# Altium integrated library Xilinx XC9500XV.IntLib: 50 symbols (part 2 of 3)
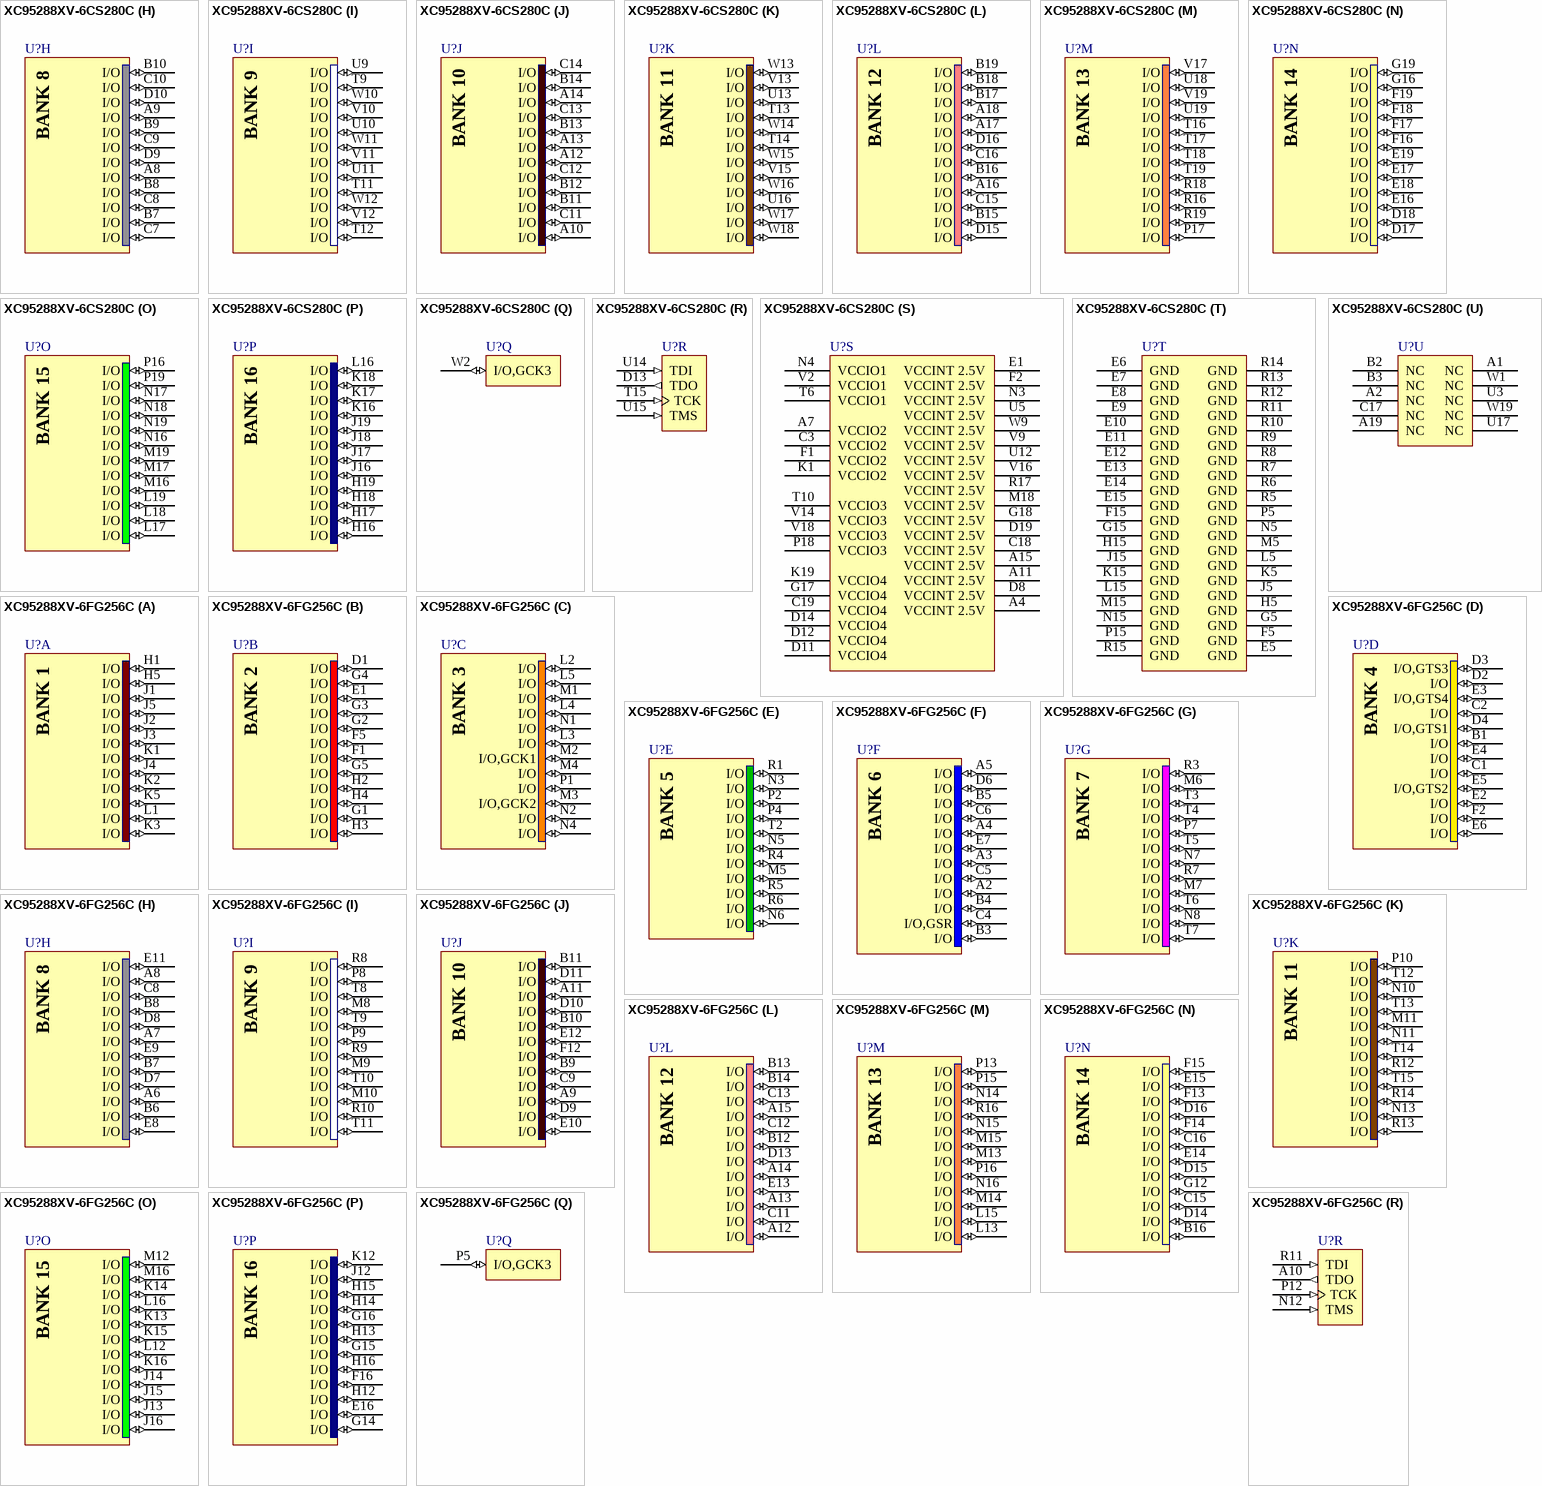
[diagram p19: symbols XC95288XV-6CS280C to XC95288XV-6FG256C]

## XC95288XV-6CS280C
designator U?
XC9500XV, 2.5V High-Performance 288 Macrocell CPLD, 192 User I/Os, 280-Ball CSBGA, Speed Grade 6, Commercial Grade
footprint CS280LAM (BGA, 280-Leads, Body 16x16mm, Pitch 0.8mm)
signal-integrity model XC95288XV_CS280 (XC9500XV)
part A pins: K2 I/O (io), K3 I/O (io), K4 I/O (io), L1 I/O (io), L2 I/O (io), L3 I/O (io), L4 I/O (io), M1 I/O (io), M2 I/O (io), M3 I/O (io), M4 I/O (io), N1 I/O (io)
part B pins: G1 I/O (io), G2 I/O (io), G3 I/O (io), G4 I/O (io), H1 I/O (io), H2 I/O (io), H3 I/O (io), H4 I/O (io), J1 I/O (io), J2 I/O (io), J3 I/O (io), J4 I/O (io)
part C pins: N2 I/O (io), P1 I/O (io), P2 I/O (io), P3 I/O (io), P4 I/O (io), R1 I/O (io), R2 I/O (io), R3 I/O,GCK1 (io), R4 I/O (io), T1 I/O,GCK2 (io), T2 I/O (io), T3 I/O (io)
part D pins: B1 I/O (io), C1 I/O,GTS4 (io), C2 I/O,GTS3 (io), D1 I/O (io), D2 I/O (io), D3 I/O,GTS1 (io), D4 I/O (io), E2 I/O,GTS2 (io), E3 I/O (io), E4 I/O (io), F3 I/O (io), F4 I/O (io)
part E pins: T4 I/O (io), T5 I/O (io), U1 I/O (io), U2 I/O (io), U4 I/O (io), V1 I/O (io), V3 I/O (io), V4 I/O (io), V5 I/O (io), W3 I/O (io), W4 I/O (io)
part F pins: A3 I/O (io), A5 I/O (io), A6 I/O (io), B4 I/O (io), B5 I/O (io), B6 I/O (io), C4 I/O,GSR (io), C5 I/O (io), C6 I/O (io), D5 I/O (io), D6 I/O (io), D7 I/O (io)
part G pins: T7 I/O (io), T8 I/O (io), U6 I/O (io), U7 I/O (io), U8 I/O (io), V6 I/O (io), V7 I/O (io), V8 I/O (io), W5 I/O (io), W6 I/O (io), W7 I/O (io), W8 I/O (io)
part H pins: A8 I/O (io), A9 I/O (io), B7 I/O (io), B8 I/O (io), B9 I/O (io), B10 I/O (io), C7 I/O (io), C8 I/O (io), C9 I/O (io), C10 I/O (io), D9 I/O (io), D10 I/O (io)
part I pins: T9 I/O (io), T11 I/O (io), T12 I/O (io), U9 I/O (io), U10 I/O (io), U11 I/O (io), V10 I/O (io), V11 I/O (io), V12 I/O (io), W10 I/O (io), W11 I/O (io), W12 I/O (io)
part J pins: A10 I/O (io), A12 I/O (io), A13 I/O (io), A14 I/O (io), B11 I/O (io), B12 I/O (io), B13 I/O (io), B14 I/O (io), C11 I/O (io), C12 I/O (io), C13 I/O (io), C14 I/O (io)
part K pins: T13 I/O (io), T14 I/O (io), U13 I/O (io), U16 I/O (io), V13 I/O (io), V15 I/O (io), W13 I/O (io), W14 I/O (io), W15 I/O (io), W16 I/O (io), W17 I/O (io), W18 I/O (io)
part L pins: A16 I/O (io), A17 I/O (io), A18 I/O (io), B15 I/O (io), B16 I/O (io), B17 I/O (io), B18 I/O (io), B19 I/O (io), C15 I/O (io), C16 I/O (io), D15 I/O (io), D16 I/O (io)
part M pins: P17 I/O (io), R16 I/O (io), R18 I/O (io), R19 I/O (io), T16 I/O (io), T17 I/O (io), T18 I/O (io), T19 I/O (io), U18 I/O (io), U19 I/O (io), V17 I/O (io), V19 I/O (io)
part N pins: D17 I/O (io), D18 I/O (io), E16 I/O (io), E17 I/O (io), E18 I/O (io), E19 I/O (io), F16 I/O (io), F17 I/O (io), F18 I/O (io), F19 I/O (io), G16 I/O (io), G19 I/O (io)
part O pins: L17 I/O (io), L18 I/O (io), L19 I/O (io), M16 I/O (io), M17 I/O (io), M19 I/O (io), N16 I/O (io), N17 I/O (io), N18 I/O (io), N19 I/O (io), P16 I/O (io), P19 I/O (io)
part P pins: H16 I/O (io), H17 I/O (io), H18 I/O (io), H19 I/O (io), J16 I/O (io), J17 I/O (io), J18 I/O (io), J19 I/O (io), K16 I/O (io), K17 I/O (io), K18 I/O (io), L16 I/O (io)
part Q pins: W2 I/O,GCK3 (io)
part R pins: D13 TDO (out), T15 TCK (in), U14 TDI (in), U15 TMS (in)
part S pins: A4 VCCINT 2.5V (power), A7 VCCIO2 (power), A11 VCCINT 2.5V (power), A15 VCCINT 2.5V (power), C3 VCCIO2 (power), C18 VCCINT 2.5V (power), C19 VCCIO4 (power), D8 VCCINT 2.5V (power), D11 VCCIO4 (power), D12 VCCIO4 (power), D14 VCCIO4 (power), D19 VCCINT 2.5V (power), E1 VCCINT 2.5V (power), F1 VCCIO2 (power), F2 VCCINT 2.5V (power), G17 VCCIO4 (power), G18 VCCINT 2.5V (power), K1 VCCIO2 (power), K19 VCCIO4 (power), M18 VCCINT 2.5V (power), N3 VCCINT 2.5V (power), N4 VCCIO1 (power), P18 VCCIO3 (power), R17 VCCINT 2.5V (power), T6 VCCIO1 (power), T10 VCCIO3 (power), U5 VCCINT 2.5V (power), U12 VCCINT 2.5V (power), V2 VCCIO1 (power), V9 VCCINT 2.5V (power), V14 VCCIO3 (power), V16 VCCINT 2.5V (power), V18 VCCIO3 (power), W9 VCCINT 2.5V (power)
part T pins: E5 GND (power), E6 GND (power), E7 GND (power), E8 GND (power), E9 GND (power), E10 GND (power), E11 GND (power), E12 GND (power), E13 GND (power), E14 GND (power), E15 GND (power), F5 GND (power), F15 GND (power), G5 GND (power), G15 GND (power), H5 GND (power), H15 GND (power), J5 GND (power), J15 GND (power), K5 GND (power), K15 GND (power), L5 GND (power), L15 GND (power), M5 GND (power), M15 GND (power), N5 GND (power), N15 GND (power), P5 GND (power), P15 GND (power), R5 GND (power), R6 GND (power), R7 GND (power), R8 GND (power), R9 GND (power), R10 GND (power), R11 GND (power), R12 GND (power), R13 GND (power), R14 GND (power), R15 GND (power)
part U pins: A1 NC, A2 NC, A19 NC, B2 NC, B3 NC, C17 NC, U3 NC, U17 NC, W1 NC, W19 NC

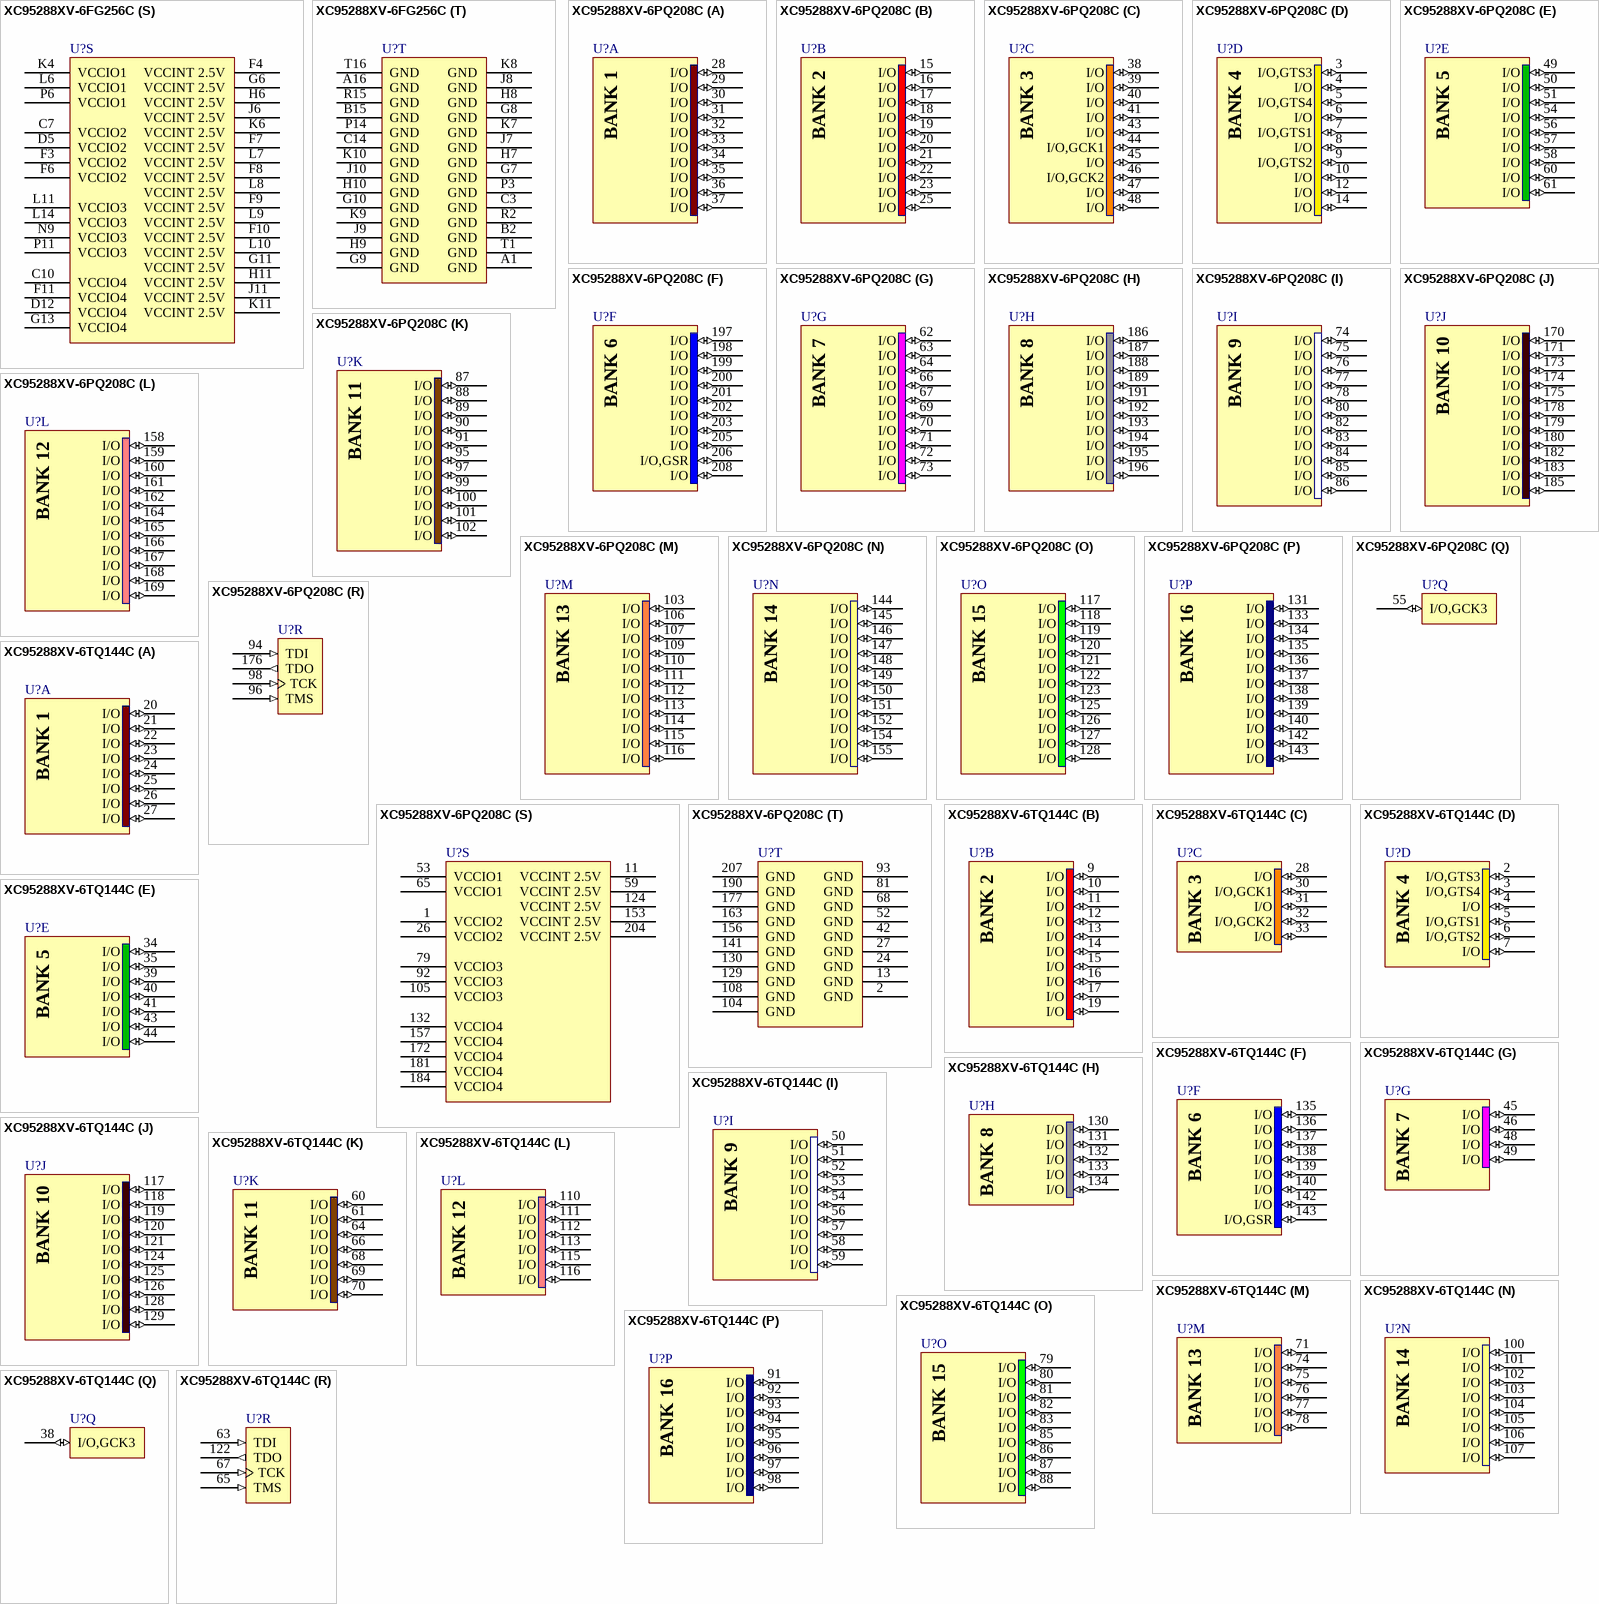
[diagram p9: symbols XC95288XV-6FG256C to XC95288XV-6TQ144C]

## XC95288XV-6FG256C
designator U?
XC9500XV, 2.5V High-Performance 288 Macrocell CPLD, 192 User I/Os, 256-Ball FBGA, Speed Grade 6, Commercial Grade
footprint FG256 (BGA, 256-Leads, Body 17x17mm, Pitch 1mm)
signal-integrity model XC95288XV_FG256 (XC9500XV)
part A pins: H1 I/O (io), H5 I/O (io), J1 I/O (io), J2 I/O (io), J3 I/O (io), J4 I/O (io), J5 I/O (io), K1 I/O (io), K2 I/O (io), K3 I/O (io), K5 I/O (io), L1 I/O (io)
part B pins: D1 I/O (io), E1 I/O (io), F1 I/O (io), F5 I/O (io), G1 I/O (io), G2 I/O (io), G3 I/O (io), G4 I/O (io), G5 I/O (io), H2 I/O (io), H3 I/O (io), H4 I/O (io)
part C pins: L2 I/O (io), L3 I/O (io), L4 I/O (io), L5 I/O (io), M1 I/O (io), M2 I/O,GCK1 (io), M3 I/O,GCK2 (io), M4 I/O (io), N1 I/O (io), N2 I/O (io), N4 I/O (io), P1 I/O (io)
part D pins: B1 I/O (io), C1 I/O (io), C2 I/O (io), D2 I/O (io), D3 I/O,GTS3 (io), D4 I/O,GTS1 (io), E2 I/O (io), E3 I/O,GTS4 (io), E4 I/O (io), E5 I/O,GTS2 (io), E6 I/O (io), F2 I/O (io)
part E pins: M5 I/O (io), N3 I/O (io), N5 I/O (io), N6 I/O (io), P2 I/O (io), P4 I/O (io), R1 I/O (io), R4 I/O (io), R5 I/O (io), R6 I/O (io), T2 I/O (io)
part F pins: A2 I/O (io), A3 I/O (io), A4 I/O (io), A5 I/O (io), B3 I/O (io), B4 I/O (io), B5 I/O (io), C4 I/O,GSR (io), C5 I/O (io), C6 I/O (io), D6 I/O (io), E7 I/O (io)
part G pins: M6 I/O (io), M7 I/O (io), N7 I/O (io), N8 I/O (io), P7 I/O (io), R3 I/O (io), R7 I/O (io), T3 I/O (io), T4 I/O (io), T5 I/O (io), T6 I/O (io), T7 I/O (io)
part H pins: A6 I/O (io), A7 I/O (io), A8 I/O (io), B6 I/O (io), B7 I/O (io), B8 I/O (io), C8 I/O (io), D7 I/O (io), D8 I/O (io), E8 I/O (io), E9 I/O (io), E11 I/O (io)
part I pins: M8 I/O (io), M9 I/O (io), M10 I/O (io), P8 I/O (io), P9 I/O (io), R8 I/O (io), R9 I/O (io), R10 I/O (io), T8 I/O (io), T9 I/O (io), T10 I/O (io), T11 I/O (io)
part J pins: A9 I/O (io), A11 I/O (io), B9 I/O (io), B10 I/O (io), B11 I/O (io), C9 I/O (io), D9 I/O (io), D10 I/O (io), D11 I/O (io), E10 I/O (io), E12 I/O (io), F12 I/O (io)
part K pins: M11 I/O (io), N10 I/O (io), N11 I/O (io), N13 I/O (io), P10 I/O (io), R12 I/O (io), R13 I/O (io), R14 I/O (io), T12 I/O (io), T13 I/O (io), T14 I/O (io), T15 I/O (io)
part L pins: A12 I/O (io), A13 I/O (io), A14 I/O (io), A15 I/O (io), B12 I/O (io), B13 I/O (io), B14 I/O (io), C11 I/O (io), C12 I/O (io), C13 I/O (io), D13 I/O (io), E13 I/O (io)
part M pins: L13 I/O (io), L15 I/O (io), M13 I/O (io), M14 I/O (io), M15 I/O (io), N14 I/O (io), N15 I/O (io), N16 I/O (io), P13 I/O (io), P15 I/O (io), P16 I/O (io), R16 I/O (io)
part N pins: B16 I/O (io), C15 I/O (io), C16 I/O (io), D14 I/O (io), D15 I/O (io), D16 I/O (io), E14 I/O (io), E15 I/O (io), F13 I/O (io), F14 I/O (io), F15 I/O (io), G12 I/O (io)
part O pins: J13 I/O (io), J14 I/O (io), J15 I/O (io), J16 I/O (io), K13 I/O (io), K14 I/O (io), K15 I/O (io), K16 I/O (io), L12 I/O (io), L16 I/O (io), M12 I/O (io), M16 I/O (io)
part P pins: E16 I/O (io), F16 I/O (io), G14 I/O (io), G15 I/O (io), G16 I/O (io), H12 I/O (io), H13 I/O (io), H14 I/O (io), H15 I/O (io), H16 I/O (io), J12 I/O (io), K12 I/O (io)
part Q pins: P5 I/O,GCK3 (io)
part R pins: A10 TDO (out), N12 TMS (in), P12 TCK (in), R11 TDI (in)
part S pins: C7 VCCIO2 (power), C10 VCCIO4 (power), D5 VCCIO2 (power), D12 VCCIO4 (power), F3 VCCIO2 (power), F4 VCCINT 2.5V (power), F6 VCCIO2 (power), F7 VCCINT 2.5V (power), F8 VCCINT 2.5V (power), F9 VCCINT 2.5V (power), F10 VCCINT 2.5V (power), F11 VCCIO4 (power), G6 VCCINT 2.5V (power), G11 VCCINT 2.5V (power), G13 VCCIO4 (power), H6 VCCINT 2.5V (power), H11 VCCINT 2.5V (power), J6 VCCINT 2.5V (power), J11 VCCINT 2.5V (power), K4 VCCIO1 (power), K6 VCCINT 2.5V (power), K11 VCCINT 2.5V (power), L6 VCCIO1 (power), L7 VCCINT 2.5V (power), L8 VCCINT 2.5V (power), L9 VCCINT 2.5V (power), L10 VCCINT 2.5V (power), L11 VCCIO3 (power), L14 VCCIO3 (power), N9 VCCIO3 (power), P6 VCCIO1 (power), P11 VCCIO3 (power)
part T pins: A1 GND (power), A16 GND (power), B2 GND (power), B15 GND (power), C3 GND (power), C14 GND (power), G7 GND (power), G8 GND (power), G9 GND (power), G10 GND (power), H7 GND (power), H8 GND (power), H9 GND (power), H10 GND (power), J7 GND (power), J8 GND (power), J9 GND (power), J10 GND (power), K7 GND (power), K8 GND (power), K9 GND (power), K10 GND (power), P3 GND (power), P14 GND (power), R2 GND (power), R15 GND (power), T1 GND (power), T16 GND (power)

## XC95288XV-6PQ208C
designator U?
XC9500XV, 2.5V High-Performance 288 Macrocell CPLD, 168 User I/Os, 208-Pin PQFP, Speed Grade 6, Commercial Grade
footprint PQ208_N (Shrink QFP, 208-Leads, Body 28x28mm, Pitch 0.5mm, IPC Medium Density)
footprint PQ208_L (Shrink QFP, 208-Leads, Body 28x28mm, Pitch 0.5mm, IPC High Density)
footprint PQ208_M (Shrink QFP, 208-Leads, Body 28x28mm, Pitch 0.5mm, IPC Low Density)
signal-integrity model XC95288XV_PQ208 (XC9500XV)
part A pins: 28 I/O (io), 29 I/O (io), 30 I/O (io), 31 I/O (io), 32 I/O (io), 33 I/O (io), 34 I/O (io), 35 I/O (io), 36 I/O (io), 37 I/O (io)
part B pins: 15 I/O (io), 16 I/O (io), 17 I/O (io), 18 I/O (io), 19 I/O (io), 20 I/O (io), 21 I/O (io), 22 I/O (io), 23 I/O (io), 25 I/O (io)
part C pins: 38 I/O (io), 39 I/O (io), 40 I/O (io), 41 I/O (io), 43 I/O (io), 44 I/O,GCK1 (io), 45 I/O (io), 46 I/O,GCK2 (io), 47 I/O (io), 48 I/O (io)
part D pins: 3 I/O,GTS3 (io), 4 I/O (io), 5 I/O,GTS4 (io), 6 I/O (io), 7 I/O,GTS1 (io), 8 I/O (io), 9 I/O,GTS2 (io), 10 I/O (io), 12 I/O (io), 14 I/O (io)
part E pins: 49 I/O (io), 50 I/O (io), 51 I/O (io), 54 I/O (io), 56 I/O (io), 57 I/O (io), 58 I/O (io), 60 I/O (io), 61 I/O (io)
part F pins: 197 I/O (io), 198 I/O (io), 199 I/O (io), 200 I/O (io), 201 I/O (io), 202 I/O (io), 203 I/O (io), 205 I/O (io), 206 I/O,GSR (io), 208 I/O (io)
part G pins: 62 I/O (io), 63 I/O (io), 64 I/O (io), 66 I/O (io), 67 I/O (io), 69 I/O (io), 70 I/O (io), 71 I/O (io), 72 I/O (io), 73 I/O (io)
part H pins: 186 I/O (io), 187 I/O (io), 188 I/O (io), 189 I/O (io), 191 I/O (io), 192 I/O (io), 193 I/O (io), 194 I/O (io), 195 I/O (io), 196 I/O (io)
part I pins: 74 I/O (io), 75 I/O (io), 76 I/O (io), 77 I/O (io), 78 I/O (io), 80 I/O (io), 82 I/O (io), 83 I/O (io), 84 I/O (io), 85 I/O (io), 86 I/O (io)
part J pins: 170 I/O (io), 171 I/O (io), 173 I/O (io), 174 I/O (io), 175 I/O (io), 178 I/O (io), 179 I/O (io), 180 I/O (io), 182 I/O (io), 183 I/O (io), 185 I/O (io)
part K pins: 87 I/O (io), 88 I/O (io), 89 I/O (io), 90 I/O (io), 91 I/O (io), 95 I/O (io), 97 I/O (io), 99 I/O (io), 100 I/O (io), 101 I/O (io), 102 I/O (io)
part L pins: 158 I/O (io), 159 I/O (io), 160 I/O (io), 161 I/O (io), 162 I/O (io), 164 I/O (io), 165 I/O (io), 166 I/O (io), 167 I/O (io), 168 I/O (io), 169 I/O (io)
part M pins: 103 I/O (io), 106 I/O (io), 107 I/O (io), 109 I/O (io), 110 I/O (io), 111 I/O (io), 112 I/O (io), 113 I/O (io), 114 I/O (io), 115 I/O (io), 116 I/O (io)
part N pins: 144 I/O (io), 145 I/O (io), 146 I/O (io), 147 I/O (io), 148 I/O (io), 149 I/O (io), 150 I/O (io), 151 I/O (io), 152 I/O (io), 154 I/O (io), 155 I/O (io)
part O pins: 117 I/O (io), 118 I/O (io), 119 I/O (io), 120 I/O (io), 121 I/O (io), 122 I/O (io), 123 I/O (io), 125 I/O (io), 126 I/O (io), 127 I/O (io), 128 I/O (io)
part P pins: 131 I/O (io), 133 I/O (io), 134 I/O (io), 135 I/O (io), 136 I/O (io), 137 I/O (io), 138 I/O (io), 139 I/O (io), 140 I/O (io), 142 I/O (io), 143 I/O (io)
part Q pins: 55 I/O,GCK3 (io)
part R pins: 94 TDI (in), 96 TMS (in), 98 TCK (in), 176 TDO (out)
part S pins: 1 VCCIO2 (power), 11 VCCINT 2.5V (power), 26 VCCIO2 (power), 53 VCCIO1 (power), 59 VCCINT 2.5V (power), 65 VCCIO1 (power), 79 VCCIO3 (power), 92 VCCIO3 (power), 105 VCCIO3 (power), 124 VCCINT 2.5V (power), 132 VCCIO4 (power), 153 VCCINT 2.5V (power), 157 VCCIO4 (power), 172 VCCIO4 (power), 181 VCCIO4 (power), 184 VCCIO4 (power), 204 VCCINT 2.5V (power)
part T pins: 2 GND (power), 13 GND (power), 24 GND (power), 27 GND (power), 42 GND (power), 52 GND (power), 68 GND (power), 81 GND (power), 93 GND (power), 104 GND (power), 108 GND (power), 129 GND (power), 130 GND (power), 141 GND (power), 156 GND (power), 163 GND (power), 177 GND (power), 190 GND (power), 207 GND (power)

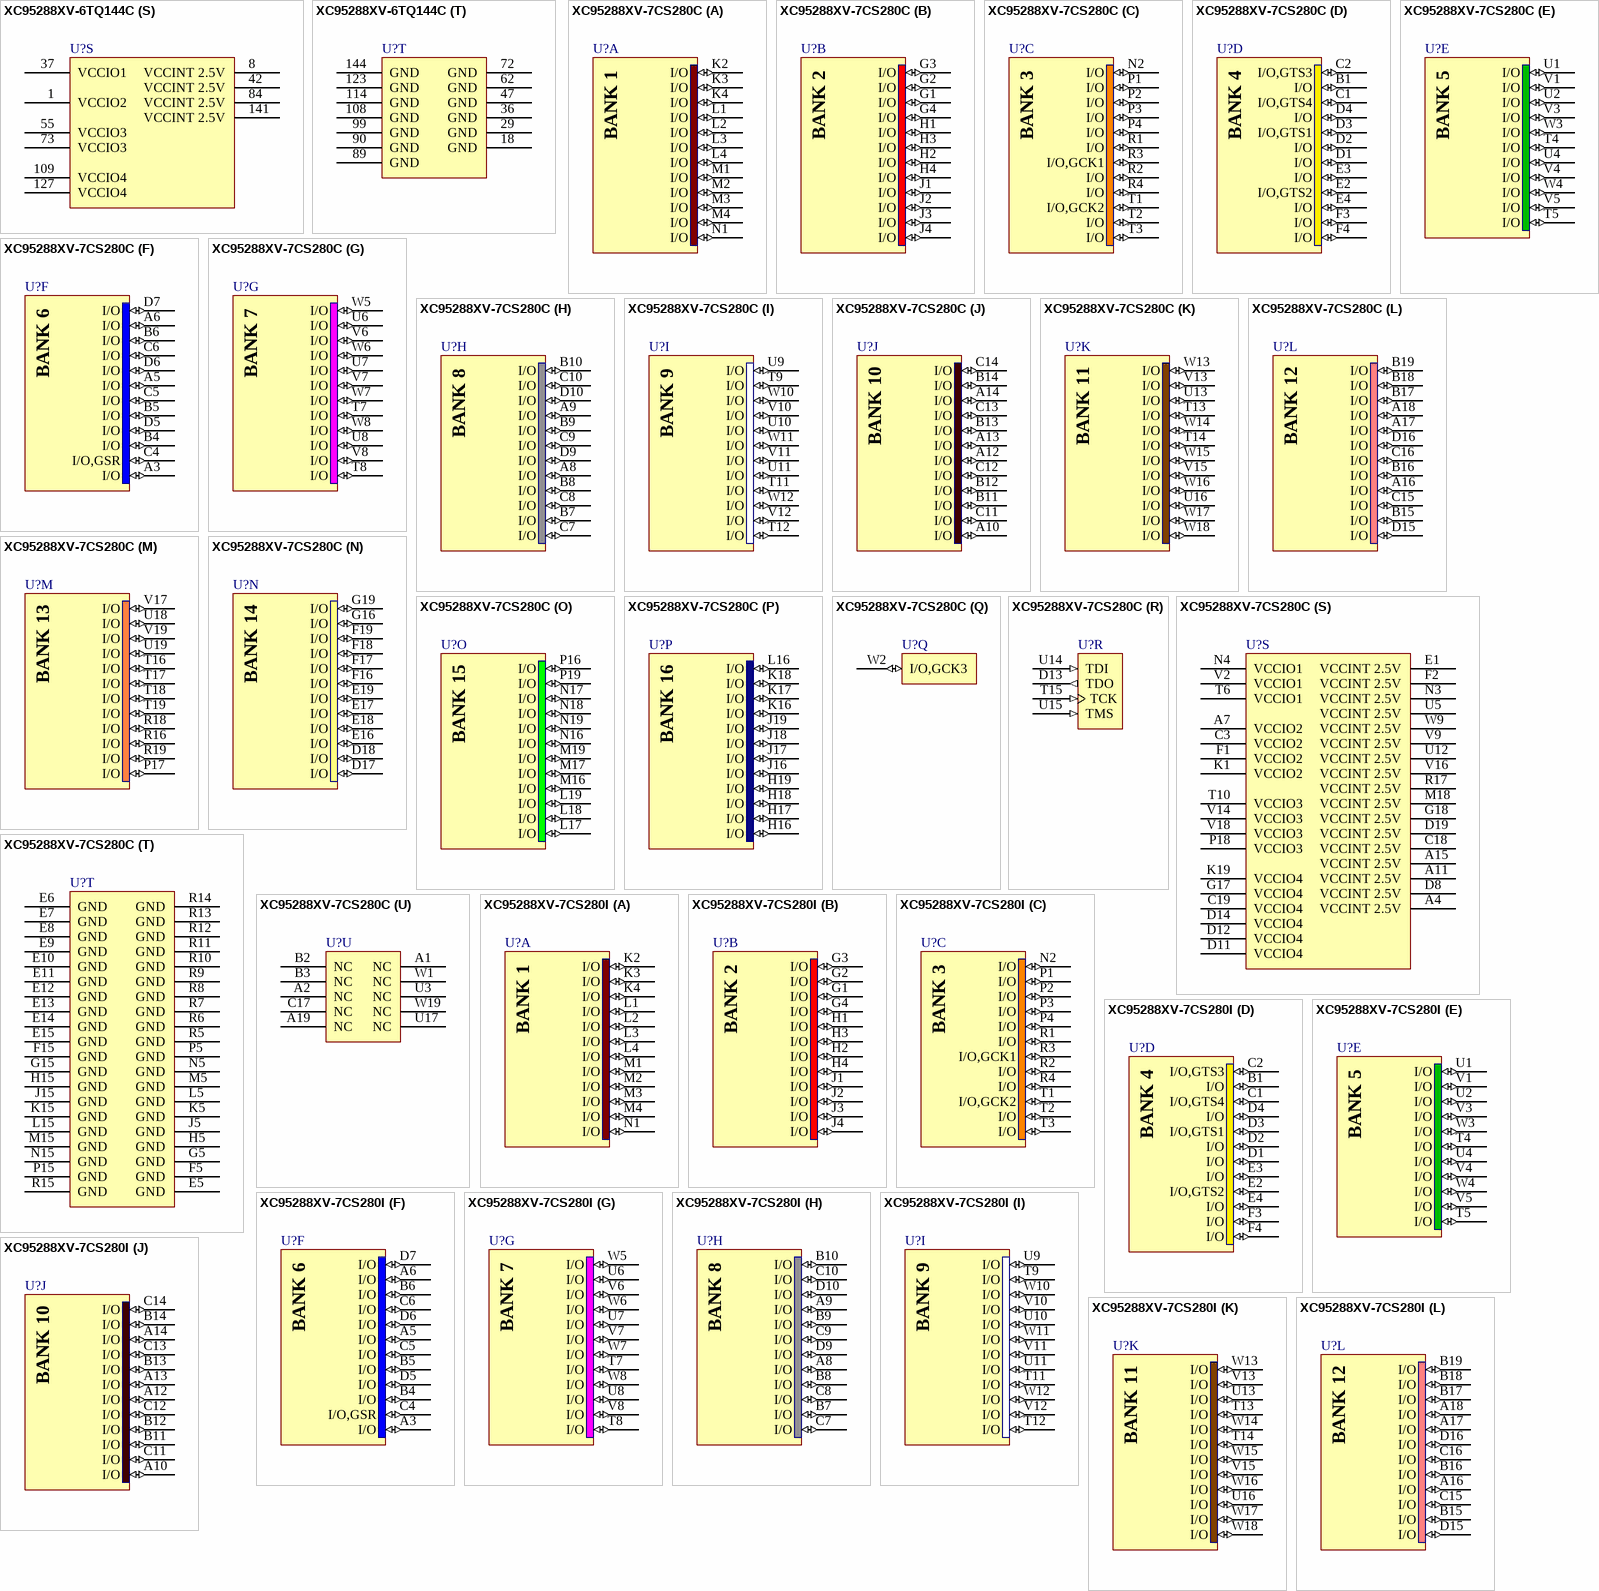
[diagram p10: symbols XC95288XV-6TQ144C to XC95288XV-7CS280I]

## XC95288XV-6TQ144C
designator U?
XC9500XV, 2.5V High-Performance 288 Macrocell CPLD, 117 User I/Os, 144-Pin TQFP, Speed Grade 6, Commercial Grade
footprint TQ144_N (Thin QFP, 144-Leads, Body 20x20mm, Pitch 0.5mm, IPC Medium Density)
footprint TQ144_L (Thin QFP, 144-Leads, Body 20x20mm, Pitch 0.5mm, IPC High Density)
footprint TQ144_M (Thin QFP, 144-Leads, Body 20x20mm, Pitch 0.5mm, IPC Low Density)
signal-integrity model XC95288XV_TQ144 (XC9500XV)
part A pins: 20 I/O (io), 21 I/O (io), 22 I/O (io), 23 I/O (io), 24 I/O (io), 25 I/O (io), 26 I/O (io), 27 I/O (io)
part B pins: 9 I/O (io), 10 I/O (io), 11 I/O (io), 12 I/O (io), 13 I/O (io), 14 I/O (io), 15 I/O (io), 16 I/O (io), 17 I/O (io), 19 I/O (io)
part C pins: 28 I/O (io), 30 I/O,GCK1 (io), 31 I/O (io), 32 I/O,GCK2 (io), 33 I/O (io)
part D pins: 2 I/O,GTS3 (io), 3 I/O,GTS4 (io), 4 I/O (io), 5 I/O,GTS1 (io), 6 I/O,GTS2 (io), 7 I/O (io)
part E pins: 34 I/O (io), 35 I/O (io), 39 I/O (io), 40 I/O (io), 41 I/O (io), 43 I/O (io), 44 I/O (io)
part F pins: 135 I/O (io), 136 I/O (io), 137 I/O (io), 138 I/O (io), 139 I/O (io), 140 I/O (io), 142 I/O (io), 143 I/O,GSR (io)
part G pins: 45 I/O (io), 46 I/O (io), 48 I/O (io), 49 I/O (io)
part H pins: 130 I/O (io), 131 I/O (io), 132 I/O (io), 133 I/O (io), 134 I/O (io)
part I pins: 50 I/O (io), 51 I/O (io), 52 I/O (io), 53 I/O (io), 54 I/O (io), 56 I/O (io), 57 I/O (io), 58 I/O (io), 59 I/O (io)
part J pins: 117 I/O (io), 118 I/O (io), 119 I/O (io), 120 I/O (io), 121 I/O (io), 124 I/O (io), 125 I/O (io), 126 I/O (io), 128 I/O (io), 129 I/O (io)
part K pins: 60 I/O (io), 61 I/O (io), 64 I/O (io), 66 I/O (io), 68 I/O (io), 69 I/O (io), 70 I/O (io)
part L pins: 110 I/O (io), 111 I/O (io), 112 I/O (io), 113 I/O (io), 115 I/O (io), 116 I/O (io)
part M pins: 71 I/O (io), 74 I/O (io), 75 I/O (io), 76 I/O (io), 77 I/O (io), 78 I/O (io)
part N pins: 100 I/O (io), 101 I/O (io), 102 I/O (io), 103 I/O (io), 104 I/O (io), 105 I/O (io), 106 I/O (io), 107 I/O (io)
part O pins: 79 I/O (io), 80 I/O (io), 81 I/O (io), 82 I/O (io), 83 I/O (io), 85 I/O (io), 86 I/O (io), 87 I/O (io), 88 I/O (io)
part P pins: 91 I/O (io), 92 I/O (io), 93 I/O (io), 94 I/O (io), 95 I/O (io), 96 I/O (io), 97 I/O (io), 98 I/O (io)
part Q pins: 38 I/O,GCK3 (io)
part R pins: 63 TDI (in), 65 TMS (in), 67 TCK (in), 122 TDO (out)
part S pins: 1 VCCIO2 (power), 8 VCCINT 2.5V (power), 37 VCCIO1 (power), 42 VCCINT 2.5V (power), 55 VCCIO3 (power), 73 VCCIO3 (power), 84 VCCINT 2.5V (power), 109 VCCIO4 (power), 127 VCCIO4 (power), 141 VCCINT 2.5V (power)
part T pins: 18 GND (power), 29 GND (power), 36 GND (power), 47 GND (power), 62 GND (power), 72 GND (power), 89 GND (power), 90 GND (power), 99 GND (power), 108 GND (power), 114 GND (power), 123 GND (power), 144 GND (power)

## XC95288XV-7CS280C
designator U?
XC9500XV, 2.5V High-Performance 288 Macrocell CPLD, 192 User I/Os, 280-Ball CSBGA, Speed Grade 7, Commercial Grade
footprint CS280LAM (BGA, 280-Leads, Body 16x16mm, Pitch 0.8mm)
signal-integrity model XC95288XV_CS280 (XC9500XV)
part A pins: K2 I/O (io), K3 I/O (io), K4 I/O (io), L1 I/O (io), L2 I/O (io), L3 I/O (io), L4 I/O (io), M1 I/O (io), M2 I/O (io), M3 I/O (io), M4 I/O (io), N1 I/O (io)
part B pins: G1 I/O (io), G2 I/O (io), G3 I/O (io), G4 I/O (io), H1 I/O (io), H2 I/O (io), H3 I/O (io), H4 I/O (io), J1 I/O (io), J2 I/O (io), J3 I/O (io), J4 I/O (io)
part C pins: N2 I/O (io), P1 I/O (io), P2 I/O (io), P3 I/O (io), P4 I/O (io), R1 I/O (io), R2 I/O (io), R3 I/O,GCK1 (io), R4 I/O (io), T1 I/O,GCK2 (io), T2 I/O (io), T3 I/O (io)
part D pins: B1 I/O (io), C1 I/O,GTS4 (io), C2 I/O,GTS3 (io), D1 I/O (io), D2 I/O (io), D3 I/O,GTS1 (io), D4 I/O (io), E2 I/O,GTS2 (io), E3 I/O (io), E4 I/O (io), F3 I/O (io), F4 I/O (io)
part E pins: T4 I/O (io), T5 I/O (io), U1 I/O (io), U2 I/O (io), U4 I/O (io), V1 I/O (io), V3 I/O (io), V4 I/O (io), V5 I/O (io), W3 I/O (io), W4 I/O (io)
part F pins: A3 I/O (io), A5 I/O (io), A6 I/O (io), B4 I/O (io), B5 I/O (io), B6 I/O (io), C4 I/O,GSR (io), C5 I/O (io), C6 I/O (io), D5 I/O (io), D6 I/O (io), D7 I/O (io)
part G pins: T7 I/O (io), T8 I/O (io), U6 I/O (io), U7 I/O (io), U8 I/O (io), V6 I/O (io), V7 I/O (io), V8 I/O (io), W5 I/O (io), W6 I/O (io), W7 I/O (io), W8 I/O (io)
part H pins: A8 I/O (io), A9 I/O (io), B7 I/O (io), B8 I/O (io), B9 I/O (io), B10 I/O (io), C7 I/O (io), C8 I/O (io), C9 I/O (io), C10 I/O (io), D9 I/O (io), D10 I/O (io)
part I pins: T9 I/O (io), T11 I/O (io), T12 I/O (io), U9 I/O (io), U10 I/O (io), U11 I/O (io), V10 I/O (io), V11 I/O (io), V12 I/O (io), W10 I/O (io), W11 I/O (io), W12 I/O (io)
part J pins: A10 I/O (io), A12 I/O (io), A13 I/O (io), A14 I/O (io), B11 I/O (io), B12 I/O (io), B13 I/O (io), B14 I/O (io), C11 I/O (io), C12 I/O (io), C13 I/O (io), C14 I/O (io)
part K pins: T13 I/O (io), T14 I/O (io), U13 I/O (io), U16 I/O (io), V13 I/O (io), V15 I/O (io), W13 I/O (io), W14 I/O (io), W15 I/O (io), W16 I/O (io), W17 I/O (io), W18 I/O (io)
part L pins: A16 I/O (io), A17 I/O (io), A18 I/O (io), B15 I/O (io), B16 I/O (io), B17 I/O (io), B18 I/O (io), B19 I/O (io), C15 I/O (io), C16 I/O (io), D15 I/O (io), D16 I/O (io)
part M pins: P17 I/O (io), R16 I/O (io), R18 I/O (io), R19 I/O (io), T16 I/O (io), T17 I/O (io), T18 I/O (io), T19 I/O (io), U18 I/O (io), U19 I/O (io), V17 I/O (io), V19 I/O (io)
part N pins: D17 I/O (io), D18 I/O (io), E16 I/O (io), E17 I/O (io), E18 I/O (io), E19 I/O (io), F16 I/O (io), F17 I/O (io), F18 I/O (io), F19 I/O (io), G16 I/O (io), G19 I/O (io)
part O pins: L17 I/O (io), L18 I/O (io), L19 I/O (io), M16 I/O (io), M17 I/O (io), M19 I/O (io), N16 I/O (io), N17 I/O (io), N18 I/O (io), N19 I/O (io), P16 I/O (io), P19 I/O (io)
part P pins: H16 I/O (io), H17 I/O (io), H18 I/O (io), H19 I/O (io), J16 I/O (io), J17 I/O (io), J18 I/O (io), J19 I/O (io), K16 I/O (io), K17 I/O (io), K18 I/O (io), L16 I/O (io)
part Q pins: W2 I/O,GCK3 (io)
part R pins: D13 TDO (out), T15 TCK (in), U14 TDI (in), U15 TMS (in)
part S pins: A4 VCCINT 2.5V (power), A7 VCCIO2 (power), A11 VCCINT 2.5V (power), A15 VCCINT 2.5V (power), C3 VCCIO2 (power), C18 VCCINT 2.5V (power), C19 VCCIO4 (power), D8 VCCINT 2.5V (power), D11 VCCIO4 (power), D12 VCCIO4 (power), D14 VCCIO4 (power), D19 VCCINT 2.5V (power), E1 VCCINT 2.5V (power), F1 VCCIO2 (power), F2 VCCINT 2.5V (power), G17 VCCIO4 (power), G18 VCCINT 2.5V (power), K1 VCCIO2 (power), K19 VCCIO4 (power), M18 VCCINT 2.5V (power), N3 VCCINT 2.5V (power), N4 VCCIO1 (power), P18 VCCIO3 (power), R17 VCCINT 2.5V (power), T6 VCCIO1 (power), T10 VCCIO3 (power), U5 VCCINT 2.5V (power), U12 VCCINT 2.5V (power), V2 VCCIO1 (power), V9 VCCINT 2.5V (power), V14 VCCIO3 (power), V16 VCCINT 2.5V (power), V18 VCCIO3 (power), W9 VCCINT 2.5V (power)
part T pins: E5 GND (power), E6 GND (power), E7 GND (power), E8 GND (power), E9 GND (power), E10 GND (power), E11 GND (power), E12 GND (power), E13 GND (power), E14 GND (power), E15 GND (power), F5 GND (power), F15 GND (power), G5 GND (power), G15 GND (power), H5 GND (power), H15 GND (power), J5 GND (power), J15 GND (power), K5 GND (power), K15 GND (power), L5 GND (power), L15 GND (power), M5 GND (power), M15 GND (power), N5 GND (power), N15 GND (power), P5 GND (power), P15 GND (power), R5 GND (power), R6 GND (power), R7 GND (power), R8 GND (power), R9 GND (power), R10 GND (power), R11 GND (power), R12 GND (power), R13 GND (power), R14 GND (power), R15 GND (power)
part U pins: A1 NC, A2 NC, A19 NC, B2 NC, B3 NC, C17 NC, U3 NC, U17 NC, W1 NC, W19 NC

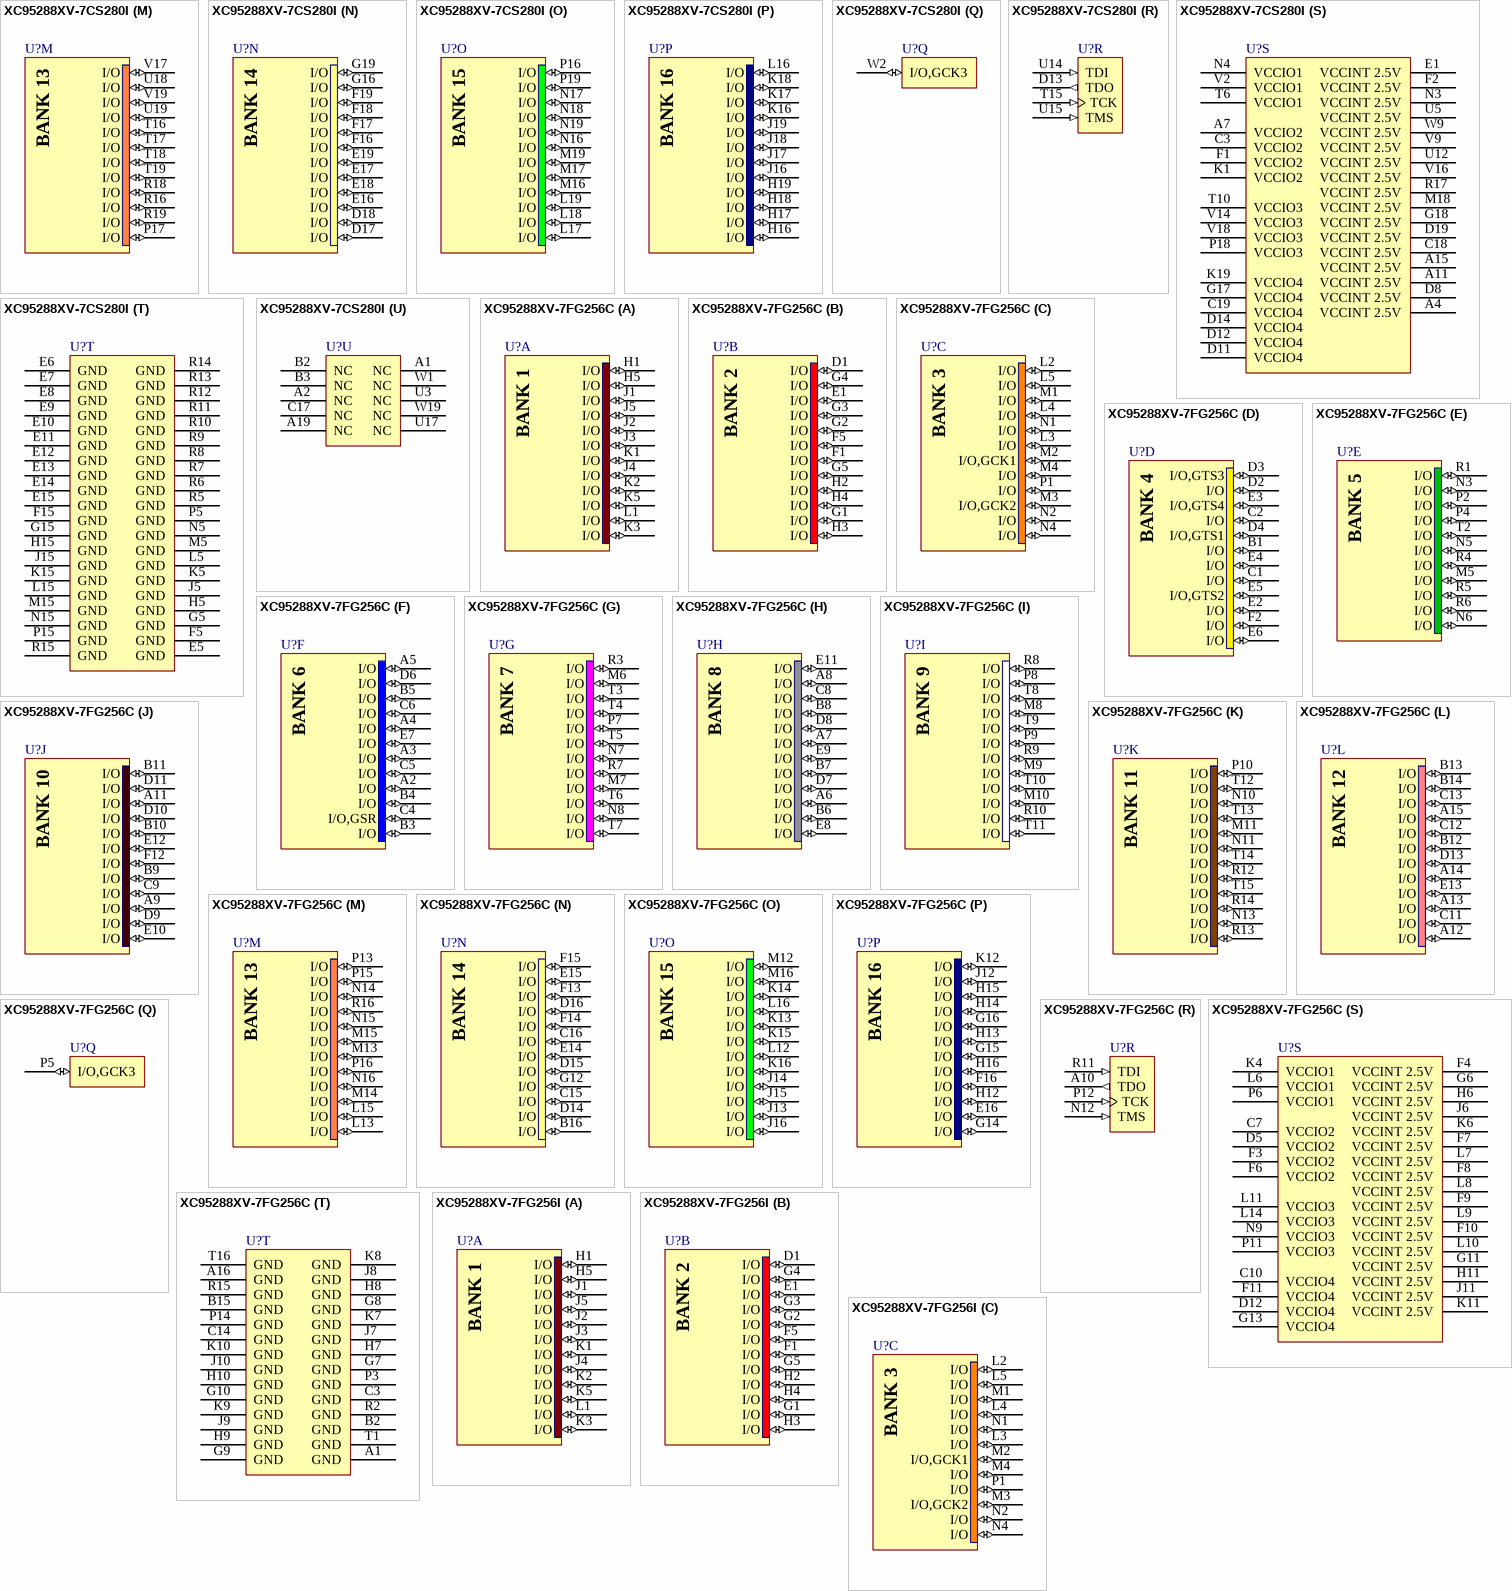
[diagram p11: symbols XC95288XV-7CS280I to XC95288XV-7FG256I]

## XC95288XV-7CS280I
designator U?
XC9500XV, 2.5V High-Performance 288 Macrocell CPLD, 192 User I/Os, 280-Ball CSBGA, Speed Grade 7, Industrial Grade
footprint CS280LAM (BGA, 280-Leads, Body 16x16mm, Pitch 0.8mm)
signal-integrity model XC95288XV_CS280 (XC9500XV)
part A pins: K2 I/O (io), K3 I/O (io), K4 I/O (io), L1 I/O (io), L2 I/O (io), L3 I/O (io), L4 I/O (io), M1 I/O (io), M2 I/O (io), M3 I/O (io), M4 I/O (io), N1 I/O (io)
part B pins: G1 I/O (io), G2 I/O (io), G3 I/O (io), G4 I/O (io), H1 I/O (io), H2 I/O (io), H3 I/O (io), H4 I/O (io), J1 I/O (io), J2 I/O (io), J3 I/O (io), J4 I/O (io)
part C pins: N2 I/O (io), P1 I/O (io), P2 I/O (io), P3 I/O (io), P4 I/O (io), R1 I/O (io), R2 I/O (io), R3 I/O,GCK1 (io), R4 I/O (io), T1 I/O,GCK2 (io), T2 I/O (io), T3 I/O (io)
part D pins: B1 I/O (io), C1 I/O,GTS4 (io), C2 I/O,GTS3 (io), D1 I/O (io), D2 I/O (io), D3 I/O,GTS1 (io), D4 I/O (io), E2 I/O,GTS2 (io), E3 I/O (io), E4 I/O (io), F3 I/O (io), F4 I/O (io)
part E pins: T4 I/O (io), T5 I/O (io), U1 I/O (io), U2 I/O (io), U4 I/O (io), V1 I/O (io), V3 I/O (io), V4 I/O (io), V5 I/O (io), W3 I/O (io), W4 I/O (io)
part F pins: A3 I/O (io), A5 I/O (io), A6 I/O (io), B4 I/O (io), B5 I/O (io), B6 I/O (io), C4 I/O,GSR (io), C5 I/O (io), C6 I/O (io), D5 I/O (io), D6 I/O (io), D7 I/O (io)
part G pins: T7 I/O (io), T8 I/O (io), U6 I/O (io), U7 I/O (io), U8 I/O (io), V6 I/O (io), V7 I/O (io), V8 I/O (io), W5 I/O (io), W6 I/O (io), W7 I/O (io), W8 I/O (io)
part H pins: A8 I/O (io), A9 I/O (io), B7 I/O (io), B8 I/O (io), B9 I/O (io), B10 I/O (io), C7 I/O (io), C8 I/O (io), C9 I/O (io), C10 I/O (io), D9 I/O (io), D10 I/O (io)
part I pins: T9 I/O (io), T11 I/O (io), T12 I/O (io), U9 I/O (io), U10 I/O (io), U11 I/O (io), V10 I/O (io), V11 I/O (io), V12 I/O (io), W10 I/O (io), W11 I/O (io), W12 I/O (io)
part J pins: A10 I/O (io), A12 I/O (io), A13 I/O (io), A14 I/O (io), B11 I/O (io), B12 I/O (io), B13 I/O (io), B14 I/O (io), C11 I/O (io), C12 I/O (io), C13 I/O (io), C14 I/O (io)
part K pins: T13 I/O (io), T14 I/O (io), U13 I/O (io), U16 I/O (io), V13 I/O (io), V15 I/O (io), W13 I/O (io), W14 I/O (io), W15 I/O (io), W16 I/O (io), W17 I/O (io), W18 I/O (io)
part L pins: A16 I/O (io), A17 I/O (io), A18 I/O (io), B15 I/O (io), B16 I/O (io), B17 I/O (io), B18 I/O (io), B19 I/O (io), C15 I/O (io), C16 I/O (io), D15 I/O (io), D16 I/O (io)
part M pins: P17 I/O (io), R16 I/O (io), R18 I/O (io), R19 I/O (io), T16 I/O (io), T17 I/O (io), T18 I/O (io), T19 I/O (io), U18 I/O (io), U19 I/O (io), V17 I/O (io), V19 I/O (io)
part N pins: D17 I/O (io), D18 I/O (io), E16 I/O (io), E17 I/O (io), E18 I/O (io), E19 I/O (io), F16 I/O (io), F17 I/O (io), F18 I/O (io), F19 I/O (io), G16 I/O (io), G19 I/O (io)
part O pins: L17 I/O (io), L18 I/O (io), L19 I/O (io), M16 I/O (io), M17 I/O (io), M19 I/O (io), N16 I/O (io), N17 I/O (io), N18 I/O (io), N19 I/O (io), P16 I/O (io), P19 I/O (io)
part P pins: H16 I/O (io), H17 I/O (io), H18 I/O (io), H19 I/O (io), J16 I/O (io), J17 I/O (io), J18 I/O (io), J19 I/O (io), K16 I/O (io), K17 I/O (io), K18 I/O (io), L16 I/O (io)
part Q pins: W2 I/O,GCK3 (io)
part R pins: D13 TDO (out), T15 TCK (in), U14 TDI (in), U15 TMS (in)
part S pins: A4 VCCINT 2.5V (power), A7 VCCIO2 (power), A11 VCCINT 2.5V (power), A15 VCCINT 2.5V (power), C3 VCCIO2 (power), C18 VCCINT 2.5V (power), C19 VCCIO4 (power), D8 VCCINT 2.5V (power), D11 VCCIO4 (power), D12 VCCIO4 (power), D14 VCCIO4 (power), D19 VCCINT 2.5V (power), E1 VCCINT 2.5V (power), F1 VCCIO2 (power), F2 VCCINT 2.5V (power), G17 VCCIO4 (power), G18 VCCINT 2.5V (power), K1 VCCIO2 (power), K19 VCCIO4 (power), M18 VCCINT 2.5V (power), N3 VCCINT 2.5V (power), N4 VCCIO1 (power), P18 VCCIO3 (power), R17 VCCINT 2.5V (power), T6 VCCIO1 (power), T10 VCCIO3 (power), U5 VCCINT 2.5V (power), U12 VCCINT 2.5V (power), V2 VCCIO1 (power), V9 VCCINT 2.5V (power), V14 VCCIO3 (power), V16 VCCINT 2.5V (power), V18 VCCIO3 (power), W9 VCCINT 2.5V (power)
part T pins: E5 GND (power), E6 GND (power), E7 GND (power), E8 GND (power), E9 GND (power), E10 GND (power), E11 GND (power), E12 GND (power), E13 GND (power), E14 GND (power), E15 GND (power), F5 GND (power), F15 GND (power), G5 GND (power), G15 GND (power), H5 GND (power), H15 GND (power), J5 GND (power), J15 GND (power), K5 GND (power), K15 GND (power), L5 GND (power), L15 GND (power), M5 GND (power), M15 GND (power), N5 GND (power), N15 GND (power), P5 GND (power), P15 GND (power), R5 GND (power), R6 GND (power), R7 GND (power), R8 GND (power), R9 GND (power), R10 GND (power), R11 GND (power), R12 GND (power), R13 GND (power), R14 GND (power), R15 GND (power)
part U pins: A1 NC, A2 NC, A19 NC, B2 NC, B3 NC, C17 NC, U3 NC, U17 NC, W1 NC, W19 NC

## XC95288XV-7FG256C
designator U?
XC9500XV, 2.5V High-Performance 288 Macrocell CPLD, 192 User I/Os, 256-Ball FBGA, Speed Grade 7, Commercial Grade
footprint FG256 (BGA, 256-Leads, Body 17x17mm, Pitch 1mm)
signal-integrity model XC95288XV_FG256 (XC9500XV)
part A pins: H1 I/O (io), H5 I/O (io), J1 I/O (io), J2 I/O (io), J3 I/O (io), J4 I/O (io), J5 I/O (io), K1 I/O (io), K2 I/O (io), K3 I/O (io), K5 I/O (io), L1 I/O (io)
part B pins: D1 I/O (io), E1 I/O (io), F1 I/O (io), F5 I/O (io), G1 I/O (io), G2 I/O (io), G3 I/O (io), G4 I/O (io), G5 I/O (io), H2 I/O (io), H3 I/O (io), H4 I/O (io)
part C pins: L2 I/O (io), L3 I/O (io), L4 I/O (io), L5 I/O (io), M1 I/O (io), M2 I/O,GCK1 (io), M3 I/O,GCK2 (io), M4 I/O (io), N1 I/O (io), N2 I/O (io), N4 I/O (io), P1 I/O (io)
part D pins: B1 I/O (io), C1 I/O (io), C2 I/O (io), D2 I/O (io), D3 I/O,GTS3 (io), D4 I/O,GTS1 (io), E2 I/O (io), E3 I/O,GTS4 (io), E4 I/O (io), E5 I/O,GTS2 (io), E6 I/O (io), F2 I/O (io)
part E pins: M5 I/O (io), N3 I/O (io), N5 I/O (io), N6 I/O (io), P2 I/O (io), P4 I/O (io), R1 I/O (io), R4 I/O (io), R5 I/O (io), R6 I/O (io), T2 I/O (io)
part F pins: A2 I/O (io), A3 I/O (io), A4 I/O (io), A5 I/O (io), B3 I/O (io), B4 I/O (io), B5 I/O (io), C4 I/O,GSR (io), C5 I/O (io), C6 I/O (io), D6 I/O (io), E7 I/O (io)
part G pins: M6 I/O (io), M7 I/O (io), N7 I/O (io), N8 I/O (io), P7 I/O (io), R3 I/O (io), R7 I/O (io), T3 I/O (io), T4 I/O (io), T5 I/O (io), T6 I/O (io), T7 I/O (io)
part H pins: A6 I/O (io), A7 I/O (io), A8 I/O (io), B6 I/O (io), B7 I/O (io), B8 I/O (io), C8 I/O (io), D7 I/O (io), D8 I/O (io), E8 I/O (io), E9 I/O (io), E11 I/O (io)
part I pins: M8 I/O (io), M9 I/O (io), M10 I/O (io), P8 I/O (io), P9 I/O (io), R8 I/O (io), R9 I/O (io), R10 I/O (io), T8 I/O (io), T9 I/O (io), T10 I/O (io), T11 I/O (io)
part J pins: A9 I/O (io), A11 I/O (io), B9 I/O (io), B10 I/O (io), B11 I/O (io), C9 I/O (io), D9 I/O (io), D10 I/O (io), D11 I/O (io), E10 I/O (io), E12 I/O (io), F12 I/O (io)
part K pins: M11 I/O (io), N10 I/O (io), N11 I/O (io), N13 I/O (io), P10 I/O (io), R12 I/O (io), R13 I/O (io), R14 I/O (io), T12 I/O (io), T13 I/O (io), T14 I/O (io), T15 I/O (io)
part L pins: A12 I/O (io), A13 I/O (io), A14 I/O (io), A15 I/O (io), B12 I/O (io), B13 I/O (io), B14 I/O (io), C11 I/O (io), C12 I/O (io), C13 I/O (io), D13 I/O (io), E13 I/O (io)
part M pins: L13 I/O (io), L15 I/O (io), M13 I/O (io), M14 I/O (io), M15 I/O (io), N14 I/O (io), N15 I/O (io), N16 I/O (io), P13 I/O (io), P15 I/O (io), P16 I/O (io), R16 I/O (io)
part N pins: B16 I/O (io), C15 I/O (io), C16 I/O (io), D14 I/O (io), D15 I/O (io), D16 I/O (io), E14 I/O (io), E15 I/O (io), F13 I/O (io), F14 I/O (io), F15 I/O (io), G12 I/O (io)
part O pins: J13 I/O (io), J14 I/O (io), J15 I/O (io), J16 I/O (io), K13 I/O (io), K14 I/O (io), K15 I/O (io), K16 I/O (io), L12 I/O (io), L16 I/O (io), M12 I/O (io), M16 I/O (io)
part P pins: E16 I/O (io), F16 I/O (io), G14 I/O (io), G15 I/O (io), G16 I/O (io), H12 I/O (io), H13 I/O (io), H14 I/O (io), H15 I/O (io), H16 I/O (io), J12 I/O (io), K12 I/O (io)
part Q pins: P5 I/O,GCK3 (io)
part R pins: A10 TDO (out), N12 TMS (in), P12 TCK (in), R11 TDI (in)
part S pins: C7 VCCIO2 (power), C10 VCCIO4 (power), D5 VCCIO2 (power), D12 VCCIO4 (power), F3 VCCIO2 (power), F4 VCCINT 2.5V (power), F6 VCCIO2 (power), F7 VCCINT 2.5V (power), F8 VCCINT 2.5V (power), F9 VCCINT 2.5V (power), F10 VCCINT 2.5V (power), F11 VCCIO4 (power), G6 VCCINT 2.5V (power), G11 VCCINT 2.5V (power), G13 VCCIO4 (power), H6 VCCINT 2.5V (power), H11 VCCINT 2.5V (power), J6 VCCINT 2.5V (power), J11 VCCINT 2.5V (power), K4 VCCIO1 (power), K6 VCCINT 2.5V (power), K11 VCCINT 2.5V (power), L6 VCCIO1 (power), L7 VCCINT 2.5V (power), L8 VCCINT 2.5V (power), L9 VCCINT 2.5V (power), L10 VCCINT 2.5V (power), L11 VCCIO3 (power), L14 VCCIO3 (power), N9 VCCIO3 (power), P6 VCCIO1 (power), P11 VCCIO3 (power)
part T pins: A1 GND (power), A16 GND (power), B2 GND (power), B15 GND (power), C3 GND (power), C14 GND (power), G7 GND (power), G8 GND (power), G9 GND (power), G10 GND (power), H7 GND (power), H8 GND (power), H9 GND (power), H10 GND (power), J7 GND (power), J8 GND (power), J9 GND (power), J10 GND (power), K7 GND (power), K8 GND (power), K9 GND (power), K10 GND (power), P3 GND (power), P14 GND (power), R2 GND (power), R15 GND (power), T1 GND (power), T16 GND (power)

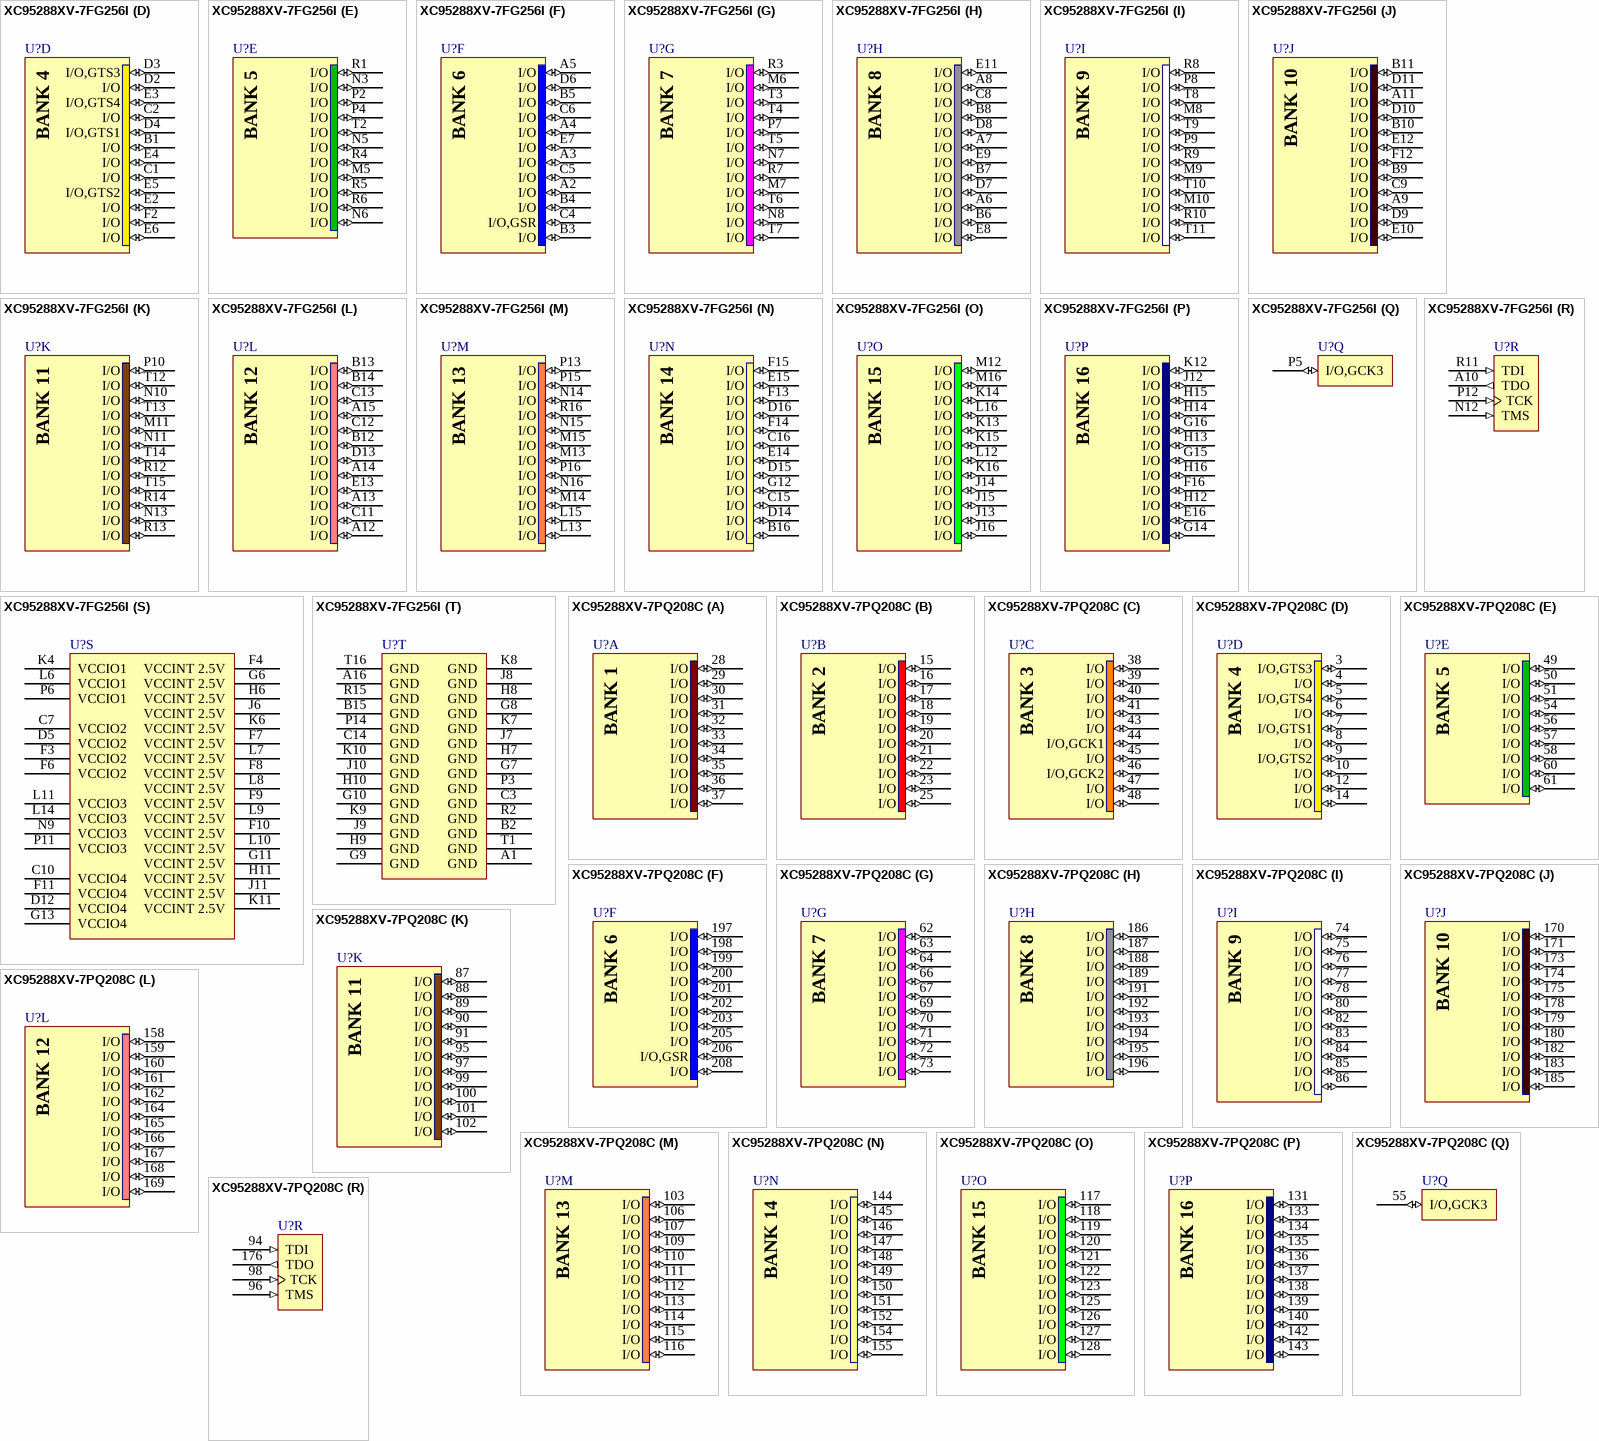
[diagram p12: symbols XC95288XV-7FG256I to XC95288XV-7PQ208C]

## XC95288XV-7FG256I
designator U?
XC9500XV, 2.5V High-Performance 288 Macrocell CPLD, 192 User I/Os, 256-Ball FBGA, Speed Grade 7, Industrial Grade
footprint FG256 (BGA, 256-Leads, Body 17x17mm, Pitch 1mm)
signal-integrity model XC95288XV_FG256 (XC9500XV)
part A pins: H1 I/O (io), H5 I/O (io), J1 I/O (io), J2 I/O (io), J3 I/O (io), J4 I/O (io), J5 I/O (io), K1 I/O (io), K2 I/O (io), K3 I/O (io), K5 I/O (io), L1 I/O (io)
part B pins: D1 I/O (io), E1 I/O (io), F1 I/O (io), F5 I/O (io), G1 I/O (io), G2 I/O (io), G3 I/O (io), G4 I/O (io), G5 I/O (io), H2 I/O (io), H3 I/O (io), H4 I/O (io)
part C pins: L2 I/O (io), L3 I/O (io), L4 I/O (io), L5 I/O (io), M1 I/O (io), M2 I/O,GCK1 (io), M3 I/O,GCK2 (io), M4 I/O (io), N1 I/O (io), N2 I/O (io), N4 I/O (io), P1 I/O (io)
part D pins: B1 I/O (io), C1 I/O (io), C2 I/O (io), D2 I/O (io), D3 I/O,GTS3 (io), D4 I/O,GTS1 (io), E2 I/O (io), E3 I/O,GTS4 (io), E4 I/O (io), E5 I/O,GTS2 (io), E6 I/O (io), F2 I/O (io)
part E pins: M5 I/O (io), N3 I/O (io), N5 I/O (io), N6 I/O (io), P2 I/O (io), P4 I/O (io), R1 I/O (io), R4 I/O (io), R5 I/O (io), R6 I/O (io), T2 I/O (io)
part F pins: A2 I/O (io), A3 I/O (io), A4 I/O (io), A5 I/O (io), B3 I/O (io), B4 I/O (io), B5 I/O (io), C4 I/O,GSR (io), C5 I/O (io), C6 I/O (io), D6 I/O (io), E7 I/O (io)
part G pins: M6 I/O (io), M7 I/O (io), N7 I/O (io), N8 I/O (io), P7 I/O (io), R3 I/O (io), R7 I/O (io), T3 I/O (io), T4 I/O (io), T5 I/O (io), T6 I/O (io), T7 I/O (io)
part H pins: A6 I/O (io), A7 I/O (io), A8 I/O (io), B6 I/O (io), B7 I/O (io), B8 I/O (io), C8 I/O (io), D7 I/O (io), D8 I/O (io), E8 I/O (io), E9 I/O (io), E11 I/O (io)
part I pins: M8 I/O (io), M9 I/O (io), M10 I/O (io), P8 I/O (io), P9 I/O (io), R8 I/O (io), R9 I/O (io), R10 I/O (io), T8 I/O (io), T9 I/O (io), T10 I/O (io), T11 I/O (io)
part J pins: A9 I/O (io), A11 I/O (io), B9 I/O (io), B10 I/O (io), B11 I/O (io), C9 I/O (io), D9 I/O (io), D10 I/O (io), D11 I/O (io), E10 I/O (io), E12 I/O (io), F12 I/O (io)
part K pins: M11 I/O (io), N10 I/O (io), N11 I/O (io), N13 I/O (io), P10 I/O (io), R12 I/O (io), R13 I/O (io), R14 I/O (io), T12 I/O (io), T13 I/O (io), T14 I/O (io), T15 I/O (io)
part L pins: A12 I/O (io), A13 I/O (io), A14 I/O (io), A15 I/O (io), B12 I/O (io), B13 I/O (io), B14 I/O (io), C11 I/O (io), C12 I/O (io), C13 I/O (io), D13 I/O (io), E13 I/O (io)
part M pins: L13 I/O (io), L15 I/O (io), M13 I/O (io), M14 I/O (io), M15 I/O (io), N14 I/O (io), N15 I/O (io), N16 I/O (io), P13 I/O (io), P15 I/O (io), P16 I/O (io), R16 I/O (io)
part N pins: B16 I/O (io), C15 I/O (io), C16 I/O (io), D14 I/O (io), D15 I/O (io), D16 I/O (io), E14 I/O (io), E15 I/O (io), F13 I/O (io), F14 I/O (io), F15 I/O (io), G12 I/O (io)
part O pins: J13 I/O (io), J14 I/O (io), J15 I/O (io), J16 I/O (io), K13 I/O (io), K14 I/O (io), K15 I/O (io), K16 I/O (io), L12 I/O (io), L16 I/O (io), M12 I/O (io), M16 I/O (io)
part P pins: E16 I/O (io), F16 I/O (io), G14 I/O (io), G15 I/O (io), G16 I/O (io), H12 I/O (io), H13 I/O (io), H14 I/O (io), H15 I/O (io), H16 I/O (io), J12 I/O (io), K12 I/O (io)
part Q pins: P5 I/O,GCK3 (io)
part R pins: A10 TDO (out), N12 TMS (in), P12 TCK (in), R11 TDI (in)
part S pins: C7 VCCIO2 (power), C10 VCCIO4 (power), D5 VCCIO2 (power), D12 VCCIO4 (power), F3 VCCIO2 (power), F4 VCCINT 2.5V (power), F6 VCCIO2 (power), F7 VCCINT 2.5V (power), F8 VCCINT 2.5V (power), F9 VCCINT 2.5V (power), F10 VCCINT 2.5V (power), F11 VCCIO4 (power), G6 VCCINT 2.5V (power), G11 VCCINT 2.5V (power), G13 VCCIO4 (power), H6 VCCINT 2.5V (power), H11 VCCINT 2.5V (power), J6 VCCINT 2.5V (power), J11 VCCINT 2.5V (power), K4 VCCIO1 (power), K6 VCCINT 2.5V (power), K11 VCCINT 2.5V (power), L6 VCCIO1 (power), L7 VCCINT 2.5V (power), L8 VCCINT 2.5V (power), L9 VCCINT 2.5V (power), L10 VCCINT 2.5V (power), L11 VCCIO3 (power), L14 VCCIO3 (power), N9 VCCIO3 (power), P6 VCCIO1 (power), P11 VCCIO3 (power)
part T pins: A1 GND (power), A16 GND (power), B2 GND (power), B15 GND (power), C3 GND (power), C14 GND (power), G7 GND (power), G8 GND (power), G9 GND (power), G10 GND (power), H7 GND (power), H8 GND (power), H9 GND (power), H10 GND (power), J7 GND (power), J8 GND (power), J9 GND (power), J10 GND (power), K7 GND (power), K8 GND (power), K9 GND (power), K10 GND (power), P3 GND (power), P14 GND (power), R2 GND (power), R15 GND (power), T1 GND (power), T16 GND (power)

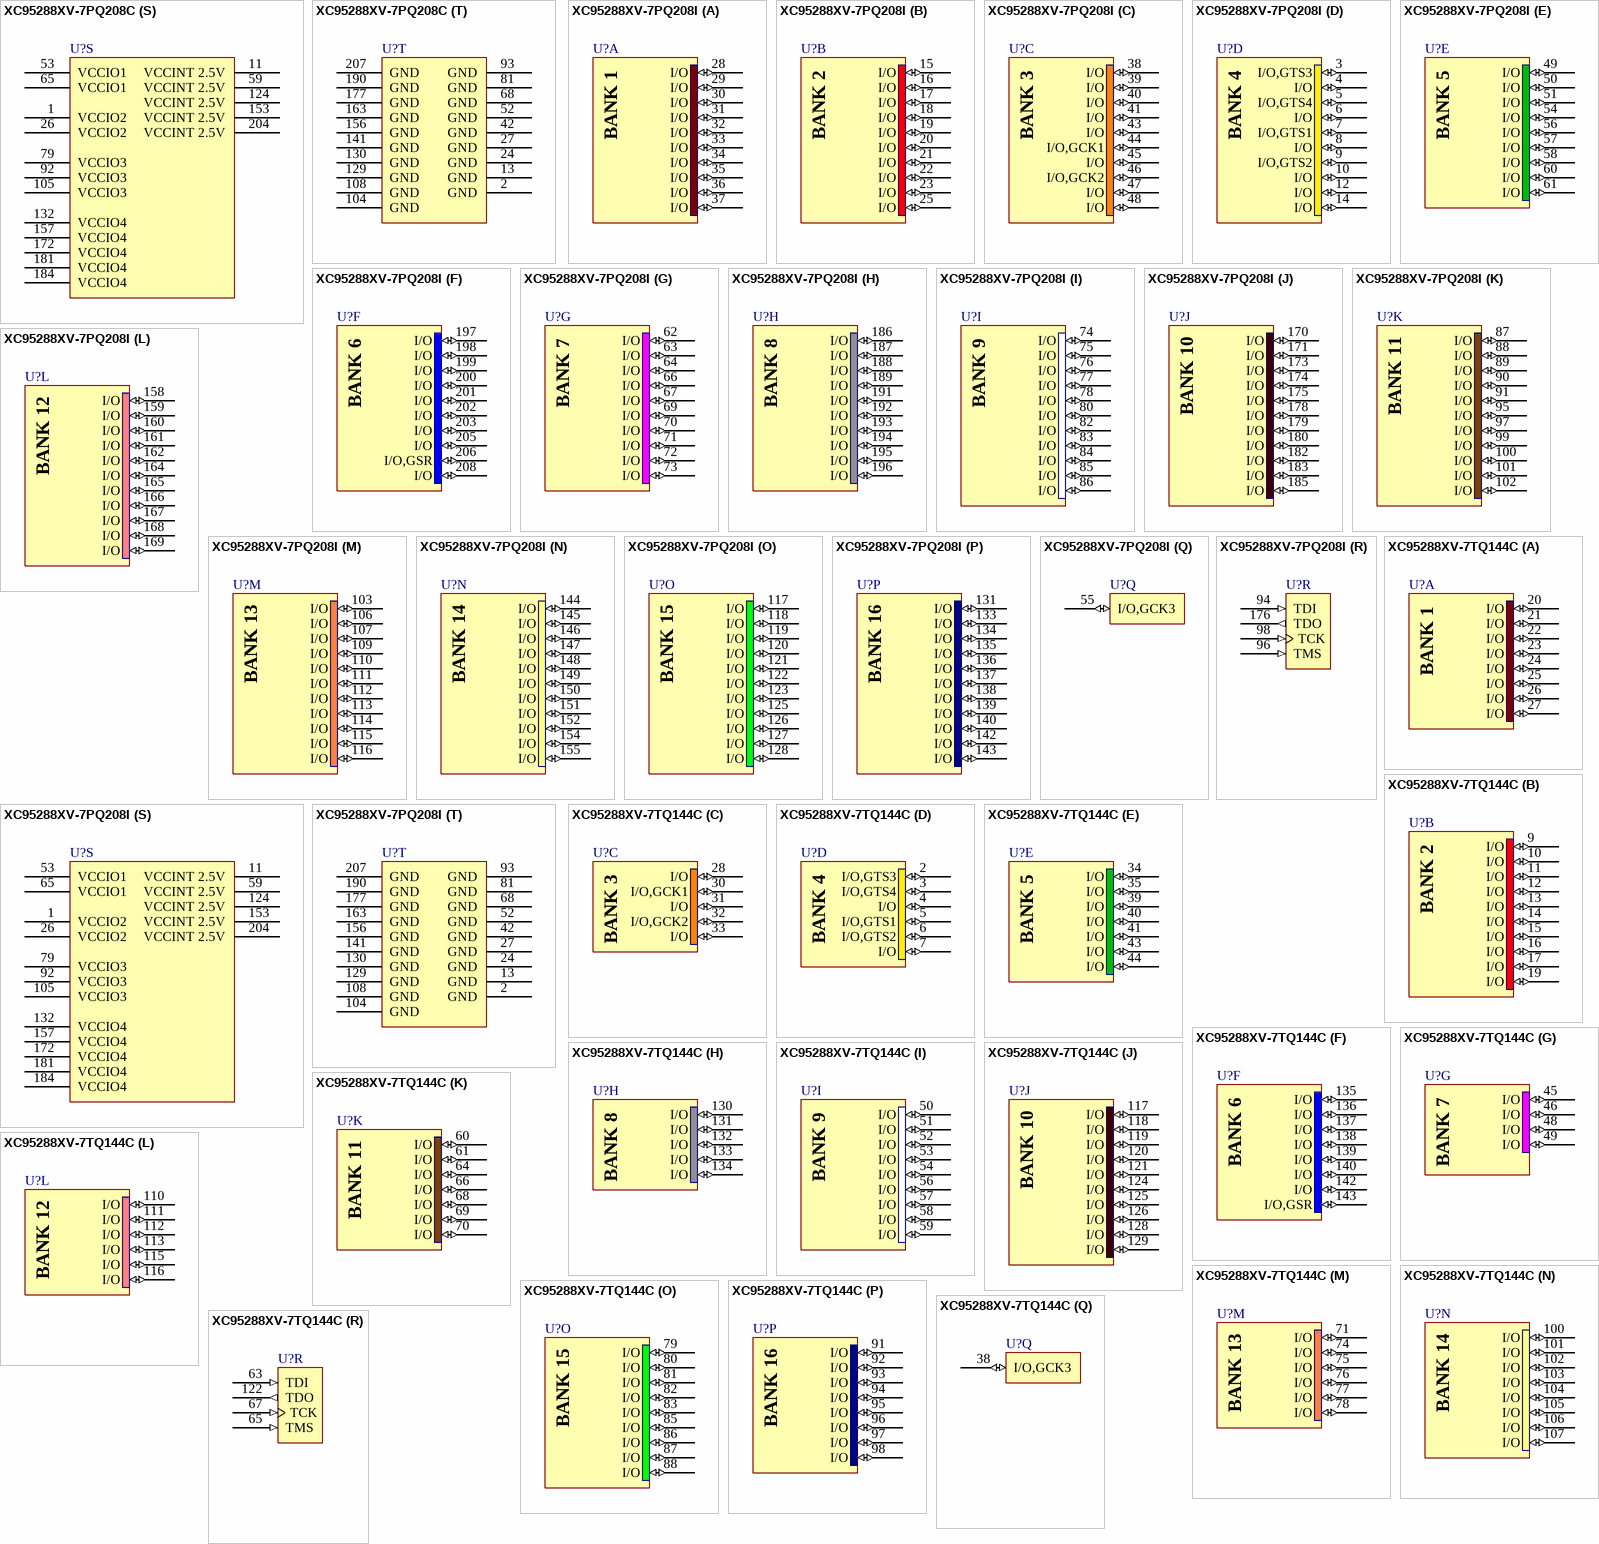
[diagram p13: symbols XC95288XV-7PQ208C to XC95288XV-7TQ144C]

## XC95288XV-7PQ208C
designator U?
XC9500XV, 2.5V High-Performance 288 Macrocell CPLD, 168 User I/Os, 208-Pin PQFP, Speed Grade 7, Commercial Grade
footprint PQ208_N (Shrink QFP, 208-Leads, Body 28x28mm, Pitch 0.5mm, IPC Medium Density)
footprint PQ208_L (Shrink QFP, 208-Leads, Body 28x28mm, Pitch 0.5mm, IPC High Density)
footprint PQ208_M (Shrink QFP, 208-Leads, Body 28x28mm, Pitch 0.5mm, IPC Low Density)
signal-integrity model XC95288XV_PQ208 (XC9500XV)
part A pins: 28 I/O (io), 29 I/O (io), 30 I/O (io), 31 I/O (io), 32 I/O (io), 33 I/O (io), 34 I/O (io), 35 I/O (io), 36 I/O (io), 37 I/O (io)
part B pins: 15 I/O (io), 16 I/O (io), 17 I/O (io), 18 I/O (io), 19 I/O (io), 20 I/O (io), 21 I/O (io), 22 I/O (io), 23 I/O (io), 25 I/O (io)
part C pins: 38 I/O (io), 39 I/O (io), 40 I/O (io), 41 I/O (io), 43 I/O (io), 44 I/O,GCK1 (io), 45 I/O (io), 46 I/O,GCK2 (io), 47 I/O (io), 48 I/O (io)
part D pins: 3 I/O,GTS3 (io), 4 I/O (io), 5 I/O,GTS4 (io), 6 I/O (io), 7 I/O,GTS1 (io), 8 I/O (io), 9 I/O,GTS2 (io), 10 I/O (io), 12 I/O (io), 14 I/O (io)
part E pins: 49 I/O (io), 50 I/O (io), 51 I/O (io), 54 I/O (io), 56 I/O (io), 57 I/O (io), 58 I/O (io), 60 I/O (io), 61 I/O (io)
part F pins: 197 I/O (io), 198 I/O (io), 199 I/O (io), 200 I/O (io), 201 I/O (io), 202 I/O (io), 203 I/O (io), 205 I/O (io), 206 I/O,GSR (io), 208 I/O (io)
part G pins: 62 I/O (io), 63 I/O (io), 64 I/O (io), 66 I/O (io), 67 I/O (io), 69 I/O (io), 70 I/O (io), 71 I/O (io), 72 I/O (io), 73 I/O (io)
part H pins: 186 I/O (io), 187 I/O (io), 188 I/O (io), 189 I/O (io), 191 I/O (io), 192 I/O (io), 193 I/O (io), 194 I/O (io), 195 I/O (io), 196 I/O (io)
part I pins: 74 I/O (io), 75 I/O (io), 76 I/O (io), 77 I/O (io), 78 I/O (io), 80 I/O (io), 82 I/O (io), 83 I/O (io), 84 I/O (io), 85 I/O (io), 86 I/O (io)
part J pins: 170 I/O (io), 171 I/O (io), 173 I/O (io), 174 I/O (io), 175 I/O (io), 178 I/O (io), 179 I/O (io), 180 I/O (io), 182 I/O (io), 183 I/O (io), 185 I/O (io)
part K pins: 87 I/O (io), 88 I/O (io), 89 I/O (io), 90 I/O (io), 91 I/O (io), 95 I/O (io), 97 I/O (io), 99 I/O (io), 100 I/O (io), 101 I/O (io), 102 I/O (io)
part L pins: 158 I/O (io), 159 I/O (io), 160 I/O (io), 161 I/O (io), 162 I/O (io), 164 I/O (io), 165 I/O (io), 166 I/O (io), 167 I/O (io), 168 I/O (io), 169 I/O (io)
part M pins: 103 I/O (io), 106 I/O (io), 107 I/O (io), 109 I/O (io), 110 I/O (io), 111 I/O (io), 112 I/O (io), 113 I/O (io), 114 I/O (io), 115 I/O (io), 116 I/O (io)
part N pins: 144 I/O (io), 145 I/O (io), 146 I/O (io), 147 I/O (io), 148 I/O (io), 149 I/O (io), 150 I/O (io), 151 I/O (io), 152 I/O (io), 154 I/O (io), 155 I/O (io)
part O pins: 117 I/O (io), 118 I/O (io), 119 I/O (io), 120 I/O (io), 121 I/O (io), 122 I/O (io), 123 I/O (io), 125 I/O (io), 126 I/O (io), 127 I/O (io), 128 I/O (io)
part P pins: 131 I/O (io), 133 I/O (io), 134 I/O (io), 135 I/O (io), 136 I/O (io), 137 I/O (io), 138 I/O (io), 139 I/O (io), 140 I/O (io), 142 I/O (io), 143 I/O (io)
part Q pins: 55 I/O,GCK3 (io)
part R pins: 94 TDI (in), 96 TMS (in), 98 TCK (in), 176 TDO (out)
part S pins: 1 VCCIO2 (power), 11 VCCINT 2.5V (power), 26 VCCIO2 (power), 53 VCCIO1 (power), 59 VCCINT 2.5V (power), 65 VCCIO1 (power), 79 VCCIO3 (power), 92 VCCIO3 (power), 105 VCCIO3 (power), 124 VCCINT 2.5V (power), 132 VCCIO4 (power), 153 VCCINT 2.5V (power), 157 VCCIO4 (power), 172 VCCIO4 (power), 181 VCCIO4 (power), 184 VCCIO4 (power), 204 VCCINT 2.5V (power)
part T pins: 2 GND (power), 13 GND (power), 24 GND (power), 27 GND (power), 42 GND (power), 52 GND (power), 68 GND (power), 81 GND (power), 93 GND (power), 104 GND (power), 108 GND (power), 129 GND (power), 130 GND (power), 141 GND (power), 156 GND (power), 163 GND (power), 177 GND (power), 190 GND (power), 207 GND (power)

## XC95288XV-7PQ208I
designator U?
XC9500XV, 2.5V High-Performance 288 Macrocell CPLD, 168 User I/Os, 208-Pin PQFP, Speed Grade 7, Industrial Grade
footprint PQ208_N (Shrink QFP, 208-Leads, Body 28x28mm, Pitch 0.5mm, IPC Medium Density)
footprint PQ208_L (Shrink QFP, 208-Leads, Body 28x28mm, Pitch 0.5mm, IPC High Density)
footprint PQ208_M (Shrink QFP, 208-Leads, Body 28x28mm, Pitch 0.5mm, IPC Low Density)
signal-integrity model XC95288XV_PQ208 (XC9500XV)
part A pins: 28 I/O (io), 29 I/O (io), 30 I/O (io), 31 I/O (io), 32 I/O (io), 33 I/O (io), 34 I/O (io), 35 I/O (io), 36 I/O (io), 37 I/O (io)
part B pins: 15 I/O (io), 16 I/O (io), 17 I/O (io), 18 I/O (io), 19 I/O (io), 20 I/O (io), 21 I/O (io), 22 I/O (io), 23 I/O (io), 25 I/O (io)
part C pins: 38 I/O (io), 39 I/O (io), 40 I/O (io), 41 I/O (io), 43 I/O (io), 44 I/O,GCK1 (io), 45 I/O (io), 46 I/O,GCK2 (io), 47 I/O (io), 48 I/O (io)
part D pins: 3 I/O,GTS3 (io), 4 I/O (io), 5 I/O,GTS4 (io), 6 I/O (io), 7 I/O,GTS1 (io), 8 I/O (io), 9 I/O,GTS2 (io), 10 I/O (io), 12 I/O (io), 14 I/O (io)
part E pins: 49 I/O (io), 50 I/O (io), 51 I/O (io), 54 I/O (io), 56 I/O (io), 57 I/O (io), 58 I/O (io), 60 I/O (io), 61 I/O (io)
part F pins: 197 I/O (io), 198 I/O (io), 199 I/O (io), 200 I/O (io), 201 I/O (io), 202 I/O (io), 203 I/O (io), 205 I/O (io), 206 I/O,GSR (io), 208 I/O (io)
part G pins: 62 I/O (io), 63 I/O (io), 64 I/O (io), 66 I/O (io), 67 I/O (io), 69 I/O (io), 70 I/O (io), 71 I/O (io), 72 I/O (io), 73 I/O (io)
part H pins: 186 I/O (io), 187 I/O (io), 188 I/O (io), 189 I/O (io), 191 I/O (io), 192 I/O (io), 193 I/O (io), 194 I/O (io), 195 I/O (io), 196 I/O (io)
part I pins: 74 I/O (io), 75 I/O (io), 76 I/O (io), 77 I/O (io), 78 I/O (io), 80 I/O (io), 82 I/O (io), 83 I/O (io), 84 I/O (io), 85 I/O (io), 86 I/O (io)
part J pins: 170 I/O (io), 171 I/O (io), 173 I/O (io), 174 I/O (io), 175 I/O (io), 178 I/O (io), 179 I/O (io), 180 I/O (io), 182 I/O (io), 183 I/O (io), 185 I/O (io)
part K pins: 87 I/O (io), 88 I/O (io), 89 I/O (io), 90 I/O (io), 91 I/O (io), 95 I/O (io), 97 I/O (io), 99 I/O (io), 100 I/O (io), 101 I/O (io), 102 I/O (io)
part L pins: 158 I/O (io), 159 I/O (io), 160 I/O (io), 161 I/O (io), 162 I/O (io), 164 I/O (io), 165 I/O (io), 166 I/O (io), 167 I/O (io), 168 I/O (io), 169 I/O (io)
part M pins: 103 I/O (io), 106 I/O (io), 107 I/O (io), 109 I/O (io), 110 I/O (io), 111 I/O (io), 112 I/O (io), 113 I/O (io), 114 I/O (io), 115 I/O (io), 116 I/O (io)
part N pins: 144 I/O (io), 145 I/O (io), 146 I/O (io), 147 I/O (io), 148 I/O (io), 149 I/O (io), 150 I/O (io), 151 I/O (io), 152 I/O (io), 154 I/O (io), 155 I/O (io)
part O pins: 117 I/O (io), 118 I/O (io), 119 I/O (io), 120 I/O (io), 121 I/O (io), 122 I/O (io), 123 I/O (io), 125 I/O (io), 126 I/O (io), 127 I/O (io), 128 I/O (io)
part P pins: 131 I/O (io), 133 I/O (io), 134 I/O (io), 135 I/O (io), 136 I/O (io), 137 I/O (io), 138 I/O (io), 139 I/O (io), 140 I/O (io), 142 I/O (io), 143 I/O (io)
part Q pins: 55 I/O,GCK3 (io)
part R pins: 94 TDI (in), 96 TMS (in), 98 TCK (in), 176 TDO (out)
part S pins: 1 VCCIO2 (power), 11 VCCINT 2.5V (power), 26 VCCIO2 (power), 53 VCCIO1 (power), 59 VCCINT 2.5V (power), 65 VCCIO1 (power), 79 VCCIO3 (power), 92 VCCIO3 (power), 105 VCCIO3 (power), 124 VCCINT 2.5V (power), 132 VCCIO4 (power), 153 VCCINT 2.5V (power), 157 VCCIO4 (power), 172 VCCIO4 (power), 181 VCCIO4 (power), 184 VCCIO4 (power), 204 VCCINT 2.5V (power)
part T pins: 2 GND (power), 13 GND (power), 24 GND (power), 27 GND (power), 42 GND (power), 52 GND (power), 68 GND (power), 81 GND (power), 93 GND (power), 104 GND (power), 108 GND (power), 129 GND (power), 130 GND (power), 141 GND (power), 156 GND (power), 163 GND (power), 177 GND (power), 190 GND (power), 207 GND (power)

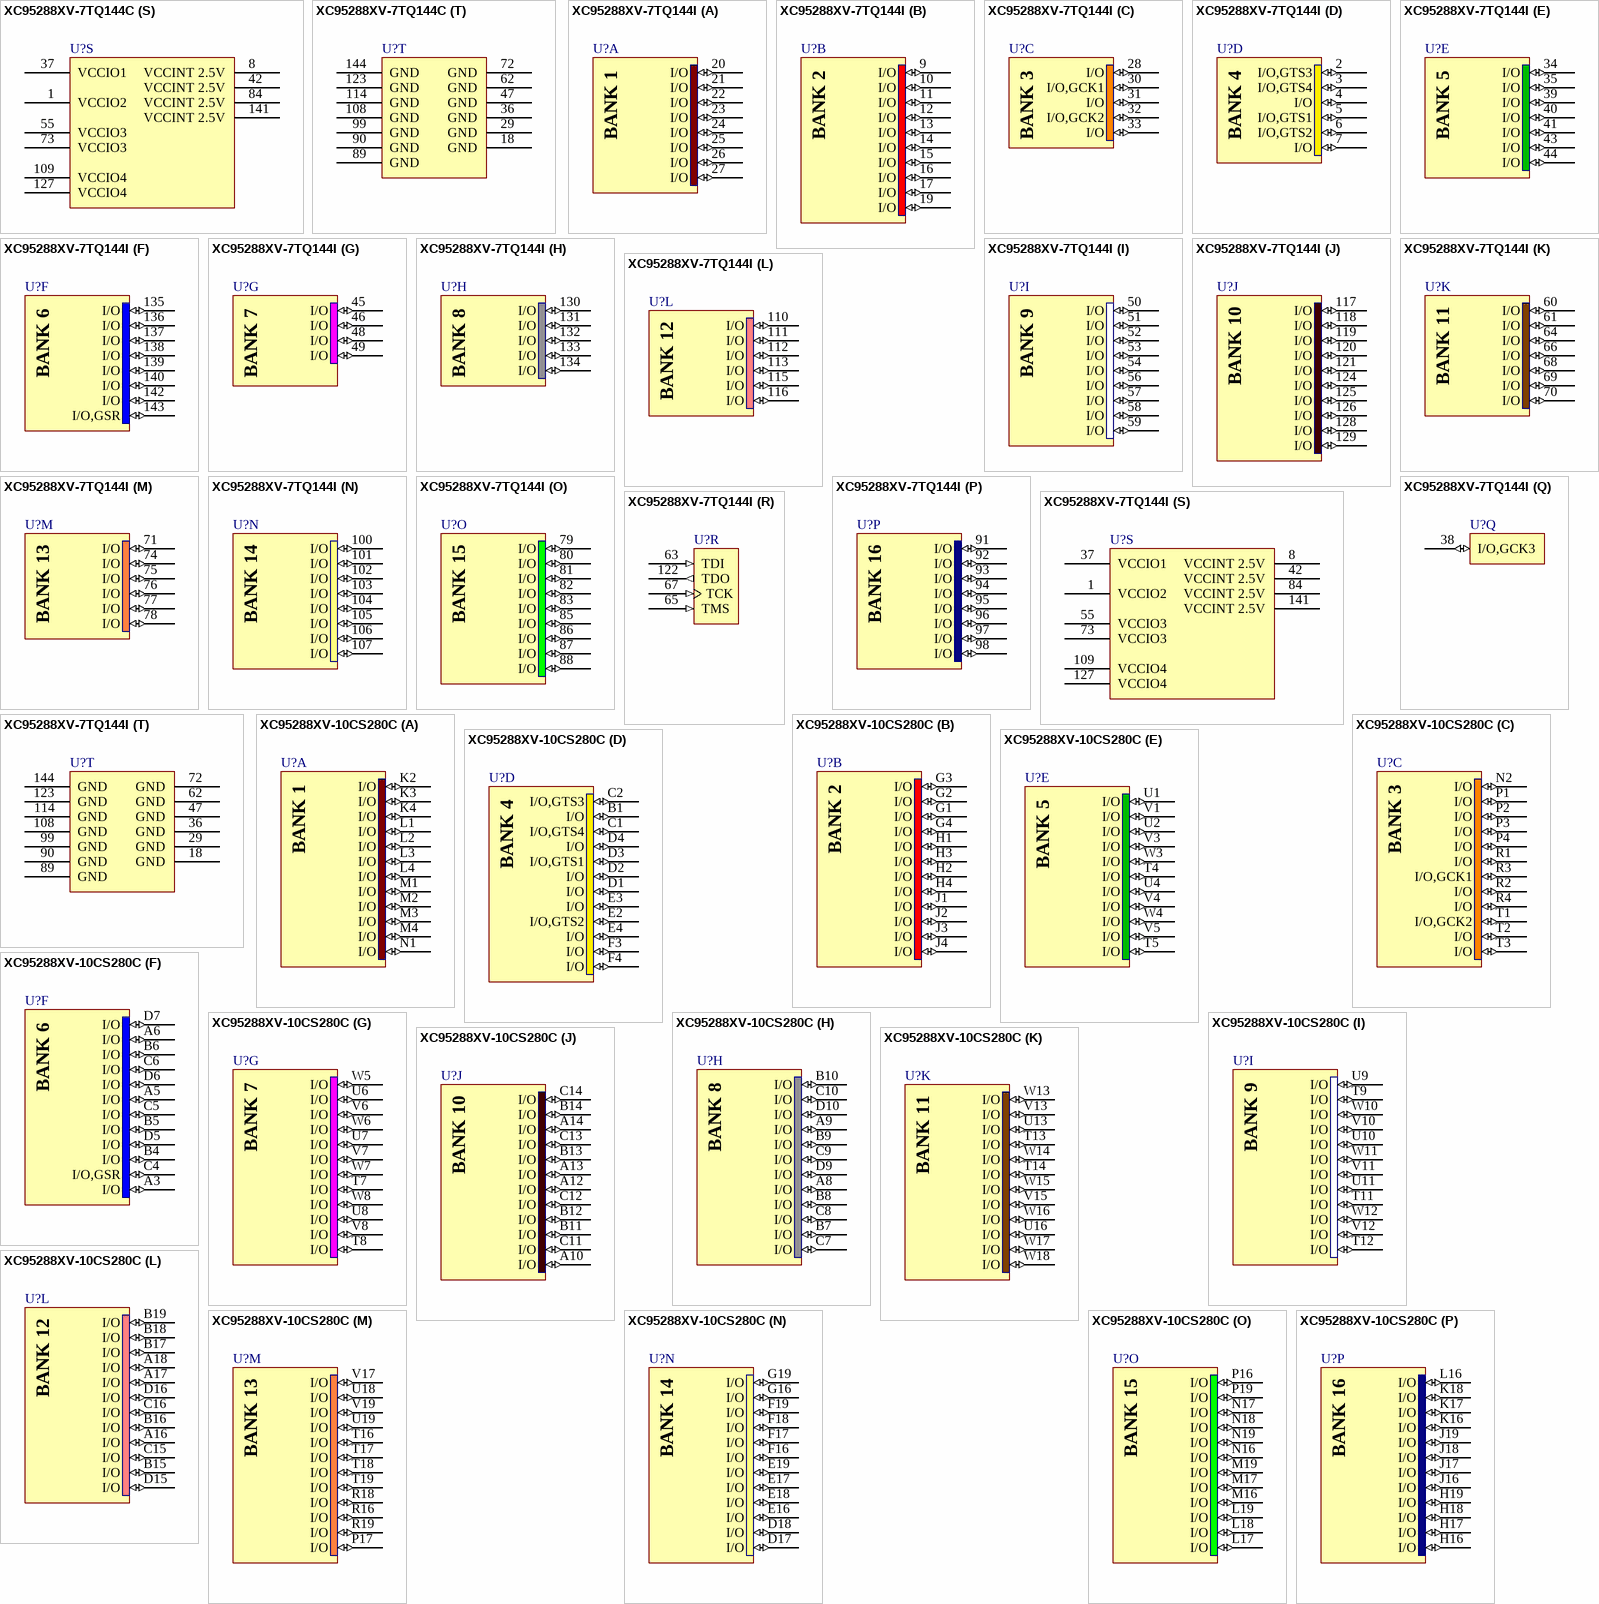
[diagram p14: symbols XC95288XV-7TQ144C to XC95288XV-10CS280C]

## XC95288XV-7TQ144C
designator U?
XC9500XV, 2.5V High-Performance 288 Macrocell CPLD, 117 User I/Os, 144-Pin TQFP, Speed Grade 7, Commercial Grade
footprint TQ144_N (Thin QFP, 144-Leads, Body 20x20mm, Pitch 0.5mm, IPC Medium Density)
footprint TQ144_L (Thin QFP, 144-Leads, Body 20x20mm, Pitch 0.5mm, IPC High Density)
footprint TQ144_M (Thin QFP, 144-Leads, Body 20x20mm, Pitch 0.5mm, IPC Low Density)
signal-integrity model XC95288XV_TQ144 (XC9500XV)
part A pins: 20 I/O (io), 21 I/O (io), 22 I/O (io), 23 I/O (io), 24 I/O (io), 25 I/O (io), 26 I/O (io), 27 I/O (io)
part B pins: 9 I/O (io), 10 I/O (io), 11 I/O (io), 12 I/O (io), 13 I/O (io), 14 I/O (io), 15 I/O (io), 16 I/O (io), 17 I/O (io), 19 I/O (io)
part C pins: 28 I/O (io), 30 I/O,GCK1 (io), 31 I/O (io), 32 I/O,GCK2 (io), 33 I/O (io)
part D pins: 2 I/O,GTS3 (io), 3 I/O,GTS4 (io), 4 I/O (io), 5 I/O,GTS1 (io), 6 I/O,GTS2 (io), 7 I/O (io)
part E pins: 34 I/O (io), 35 I/O (io), 39 I/O (io), 40 I/O (io), 41 I/O (io), 43 I/O (io), 44 I/O (io)
part F pins: 135 I/O (io), 136 I/O (io), 137 I/O (io), 138 I/O (io), 139 I/O (io), 140 I/O (io), 142 I/O (io), 143 I/O,GSR (io)
part G pins: 45 I/O (io), 46 I/O (io), 48 I/O (io), 49 I/O (io)
part H pins: 130 I/O (io), 131 I/O (io), 132 I/O (io), 133 I/O (io), 134 I/O (io)
part I pins: 50 I/O (io), 51 I/O (io), 52 I/O (io), 53 I/O (io), 54 I/O (io), 56 I/O (io), 57 I/O (io), 58 I/O (io), 59 I/O (io)
part J pins: 117 I/O (io), 118 I/O (io), 119 I/O (io), 120 I/O (io), 121 I/O (io), 124 I/O (io), 125 I/O (io), 126 I/O (io), 128 I/O (io), 129 I/O (io)
part K pins: 60 I/O (io), 61 I/O (io), 64 I/O (io), 66 I/O (io), 68 I/O (io), 69 I/O (io), 70 I/O (io)
part L pins: 110 I/O (io), 111 I/O (io), 112 I/O (io), 113 I/O (io), 115 I/O (io), 116 I/O (io)
part M pins: 71 I/O (io), 74 I/O (io), 75 I/O (io), 76 I/O (io), 77 I/O (io), 78 I/O (io)
part N pins: 100 I/O (io), 101 I/O (io), 102 I/O (io), 103 I/O (io), 104 I/O (io), 105 I/O (io), 106 I/O (io), 107 I/O (io)
part O pins: 79 I/O (io), 80 I/O (io), 81 I/O (io), 82 I/O (io), 83 I/O (io), 85 I/O (io), 86 I/O (io), 87 I/O (io), 88 I/O (io)
part P pins: 91 I/O (io), 92 I/O (io), 93 I/O (io), 94 I/O (io), 95 I/O (io), 96 I/O (io), 97 I/O (io), 98 I/O (io)
part Q pins: 38 I/O,GCK3 (io)
part R pins: 63 TDI (in), 65 TMS (in), 67 TCK (in), 122 TDO (out)
part S pins: 1 VCCIO2 (power), 8 VCCINT 2.5V (power), 37 VCCIO1 (power), 42 VCCINT 2.5V (power), 55 VCCIO3 (power), 73 VCCIO3 (power), 84 VCCINT 2.5V (power), 109 VCCIO4 (power), 127 VCCIO4 (power), 141 VCCINT 2.5V (power)
part T pins: 18 GND (power), 29 GND (power), 36 GND (power), 47 GND (power), 62 GND (power), 72 GND (power), 89 GND (power), 90 GND (power), 99 GND (power), 108 GND (power), 114 GND (power), 123 GND (power), 144 GND (power)

## XC95288XV-7TQ144I
designator U?
XC9500XV, 2.5V High-Performance 288 Macrocell CPLD, 117 User I/Os, 144-Pin TQFP, Speed Grade 7, Industrial Grade
footprint TQ144_N (Thin QFP, 144-Leads, Body 20x20mm, Pitch 0.5mm, IPC Medium Density)
footprint TQ144_L (Thin QFP, 144-Leads, Body 20x20mm, Pitch 0.5mm, IPC High Density)
footprint TQ144_M (Thin QFP, 144-Leads, Body 20x20mm, Pitch 0.5mm, IPC Low Density)
signal-integrity model XC95288XV_TQ144 (XC9500XV)
part A pins: 20 I/O (io), 21 I/O (io), 22 I/O (io), 23 I/O (io), 24 I/O (io), 25 I/O (io), 26 I/O (io), 27 I/O (io)
part B pins: 9 I/O (io), 10 I/O (io), 11 I/O (io), 12 I/O (io), 13 I/O (io), 14 I/O (io), 15 I/O (io), 16 I/O (io), 17 I/O (io), 19 I/O (io)
part C pins: 28 I/O (io), 30 I/O,GCK1 (io), 31 I/O (io), 32 I/O,GCK2 (io), 33 I/O (io)
part D pins: 2 I/O,GTS3 (io), 3 I/O,GTS4 (io), 4 I/O (io), 5 I/O,GTS1 (io), 6 I/O,GTS2 (io), 7 I/O (io)
part E pins: 34 I/O (io), 35 I/O (io), 39 I/O (io), 40 I/O (io), 41 I/O (io), 43 I/O (io), 44 I/O (io)
part F pins: 135 I/O (io), 136 I/O (io), 137 I/O (io), 138 I/O (io), 139 I/O (io), 140 I/O (io), 142 I/O (io), 143 I/O,GSR (io)
part G pins: 45 I/O (io), 46 I/O (io), 48 I/O (io), 49 I/O (io)
part H pins: 130 I/O (io), 131 I/O (io), 132 I/O (io), 133 I/O (io), 134 I/O (io)
part I pins: 50 I/O (io), 51 I/O (io), 52 I/O (io), 53 I/O (io), 54 I/O (io), 56 I/O (io), 57 I/O (io), 58 I/O (io), 59 I/O (io)
part J pins: 117 I/O (io), 118 I/O (io), 119 I/O (io), 120 I/O (io), 121 I/O (io), 124 I/O (io), 125 I/O (io), 126 I/O (io), 128 I/O (io), 129 I/O (io)
part K pins: 60 I/O (io), 61 I/O (io), 64 I/O (io), 66 I/O (io), 68 I/O (io), 69 I/O (io), 70 I/O (io)
part L pins: 110 I/O (io), 111 I/O (io), 112 I/O (io), 113 I/O (io), 115 I/O (io), 116 I/O (io)
part M pins: 71 I/O (io), 74 I/O (io), 75 I/O (io), 76 I/O (io), 77 I/O (io), 78 I/O (io)
part N pins: 100 I/O (io), 101 I/O (io), 102 I/O (io), 103 I/O (io), 104 I/O (io), 105 I/O (io), 106 I/O (io), 107 I/O (io)
part O pins: 79 I/O (io), 80 I/O (io), 81 I/O (io), 82 I/O (io), 83 I/O (io), 85 I/O (io), 86 I/O (io), 87 I/O (io), 88 I/O (io)
part P pins: 91 I/O (io), 92 I/O (io), 93 I/O (io), 94 I/O (io), 95 I/O (io), 96 I/O (io), 97 I/O (io), 98 I/O (io)
part Q pins: 38 I/O,GCK3 (io)
part R pins: 63 TDI (in), 65 TMS (in), 67 TCK (in), 122 TDO (out)
part S pins: 1 VCCIO2 (power), 8 VCCINT 2.5V (power), 37 VCCIO1 (power), 42 VCCINT 2.5V (power), 55 VCCIO3 (power), 73 VCCIO3 (power), 84 VCCINT 2.5V (power), 109 VCCIO4 (power), 127 VCCIO4 (power), 141 VCCINT 2.5V (power)
part T pins: 18 GND (power), 29 GND (power), 36 GND (power), 47 GND (power), 62 GND (power), 72 GND (power), 89 GND (power), 90 GND (power), 99 GND (power), 108 GND (power), 114 GND (power), 123 GND (power), 144 GND (power)

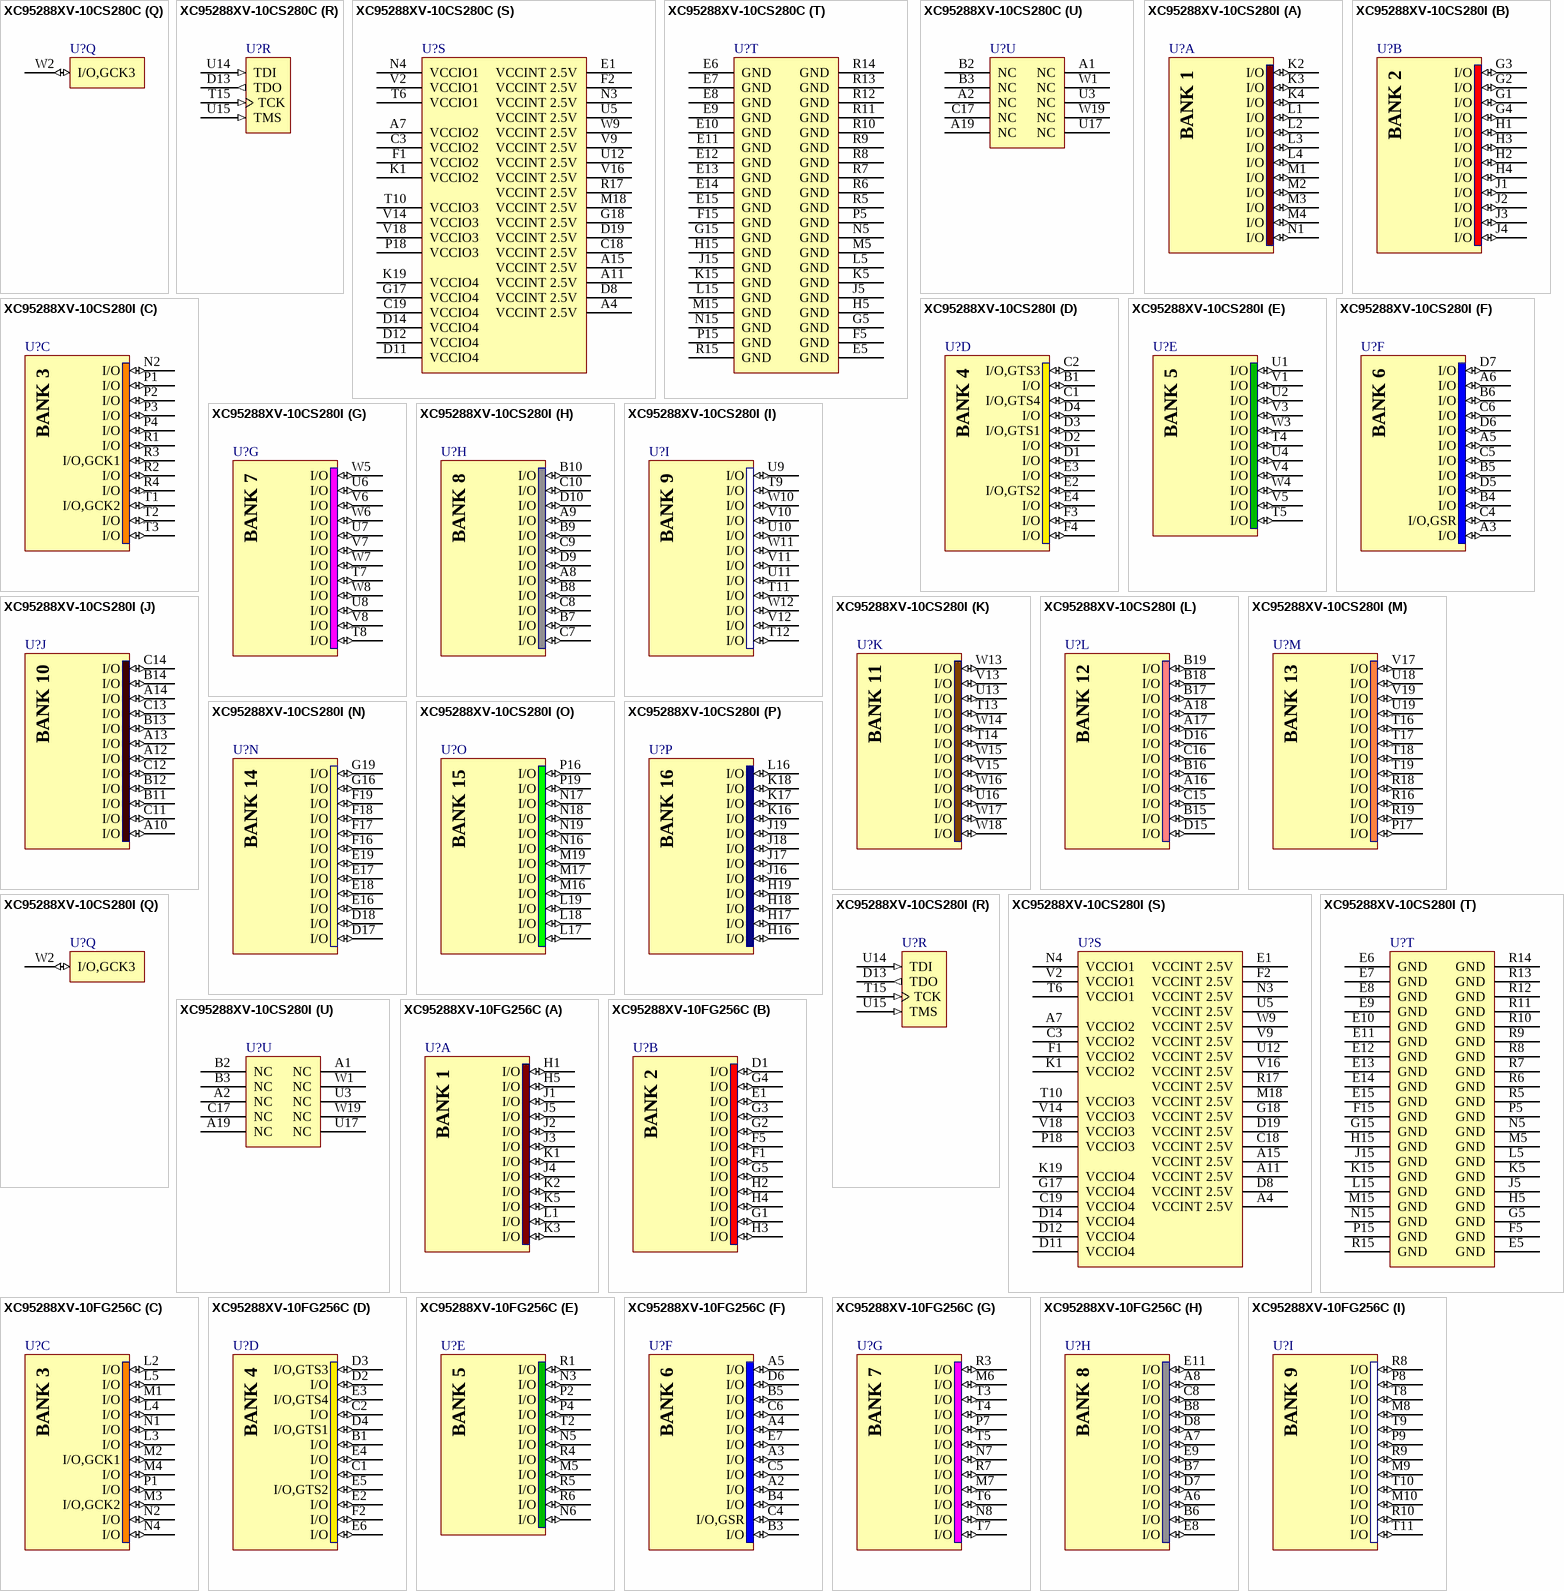
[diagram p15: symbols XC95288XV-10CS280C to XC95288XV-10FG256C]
